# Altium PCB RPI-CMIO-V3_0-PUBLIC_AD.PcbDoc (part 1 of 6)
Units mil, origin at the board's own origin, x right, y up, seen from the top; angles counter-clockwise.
Board outline 3295.4 x 4105.44 mil, 6 copper layers (TOP, GNDT, PWRT, PWRB, GNDB, BOTTOM); 114 components, 152 nets, 703 pads, 476 vias.
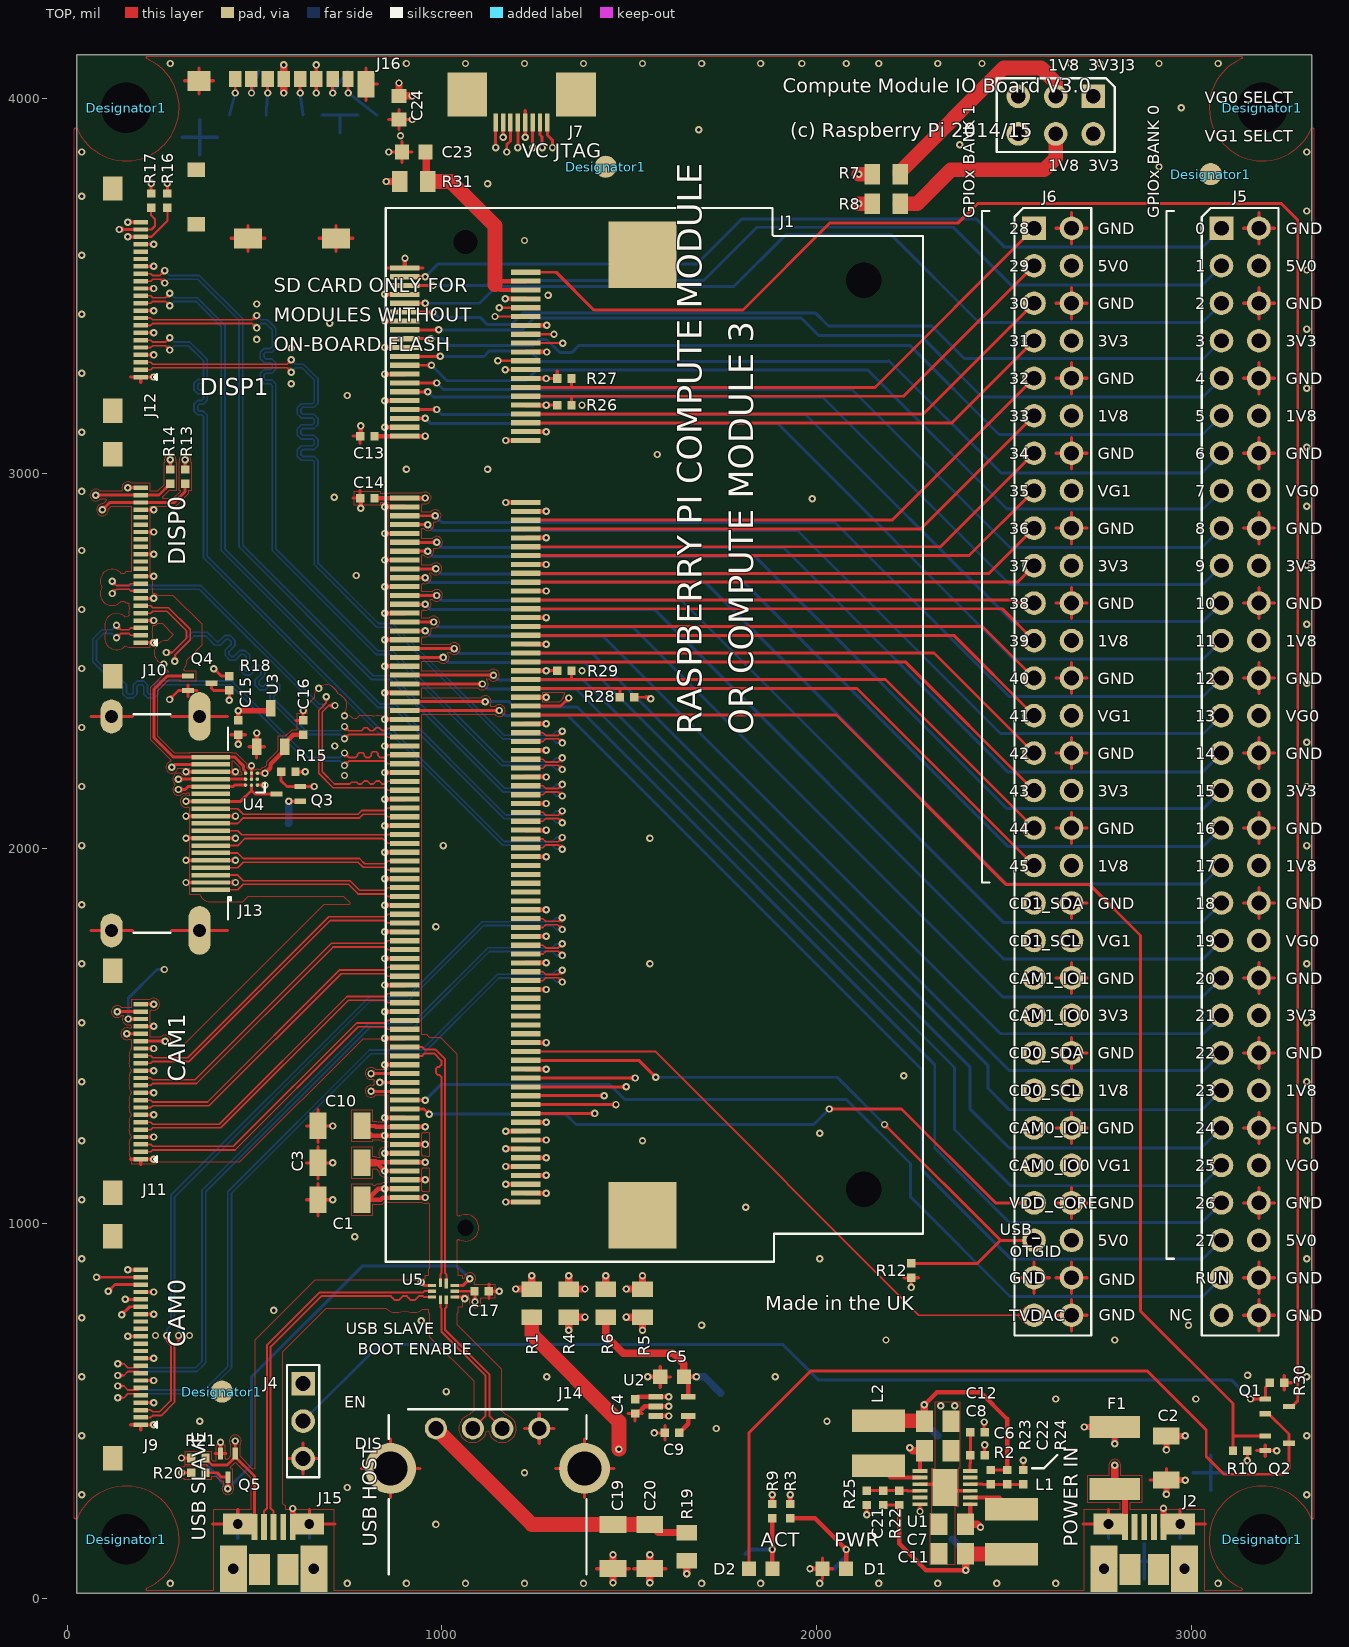
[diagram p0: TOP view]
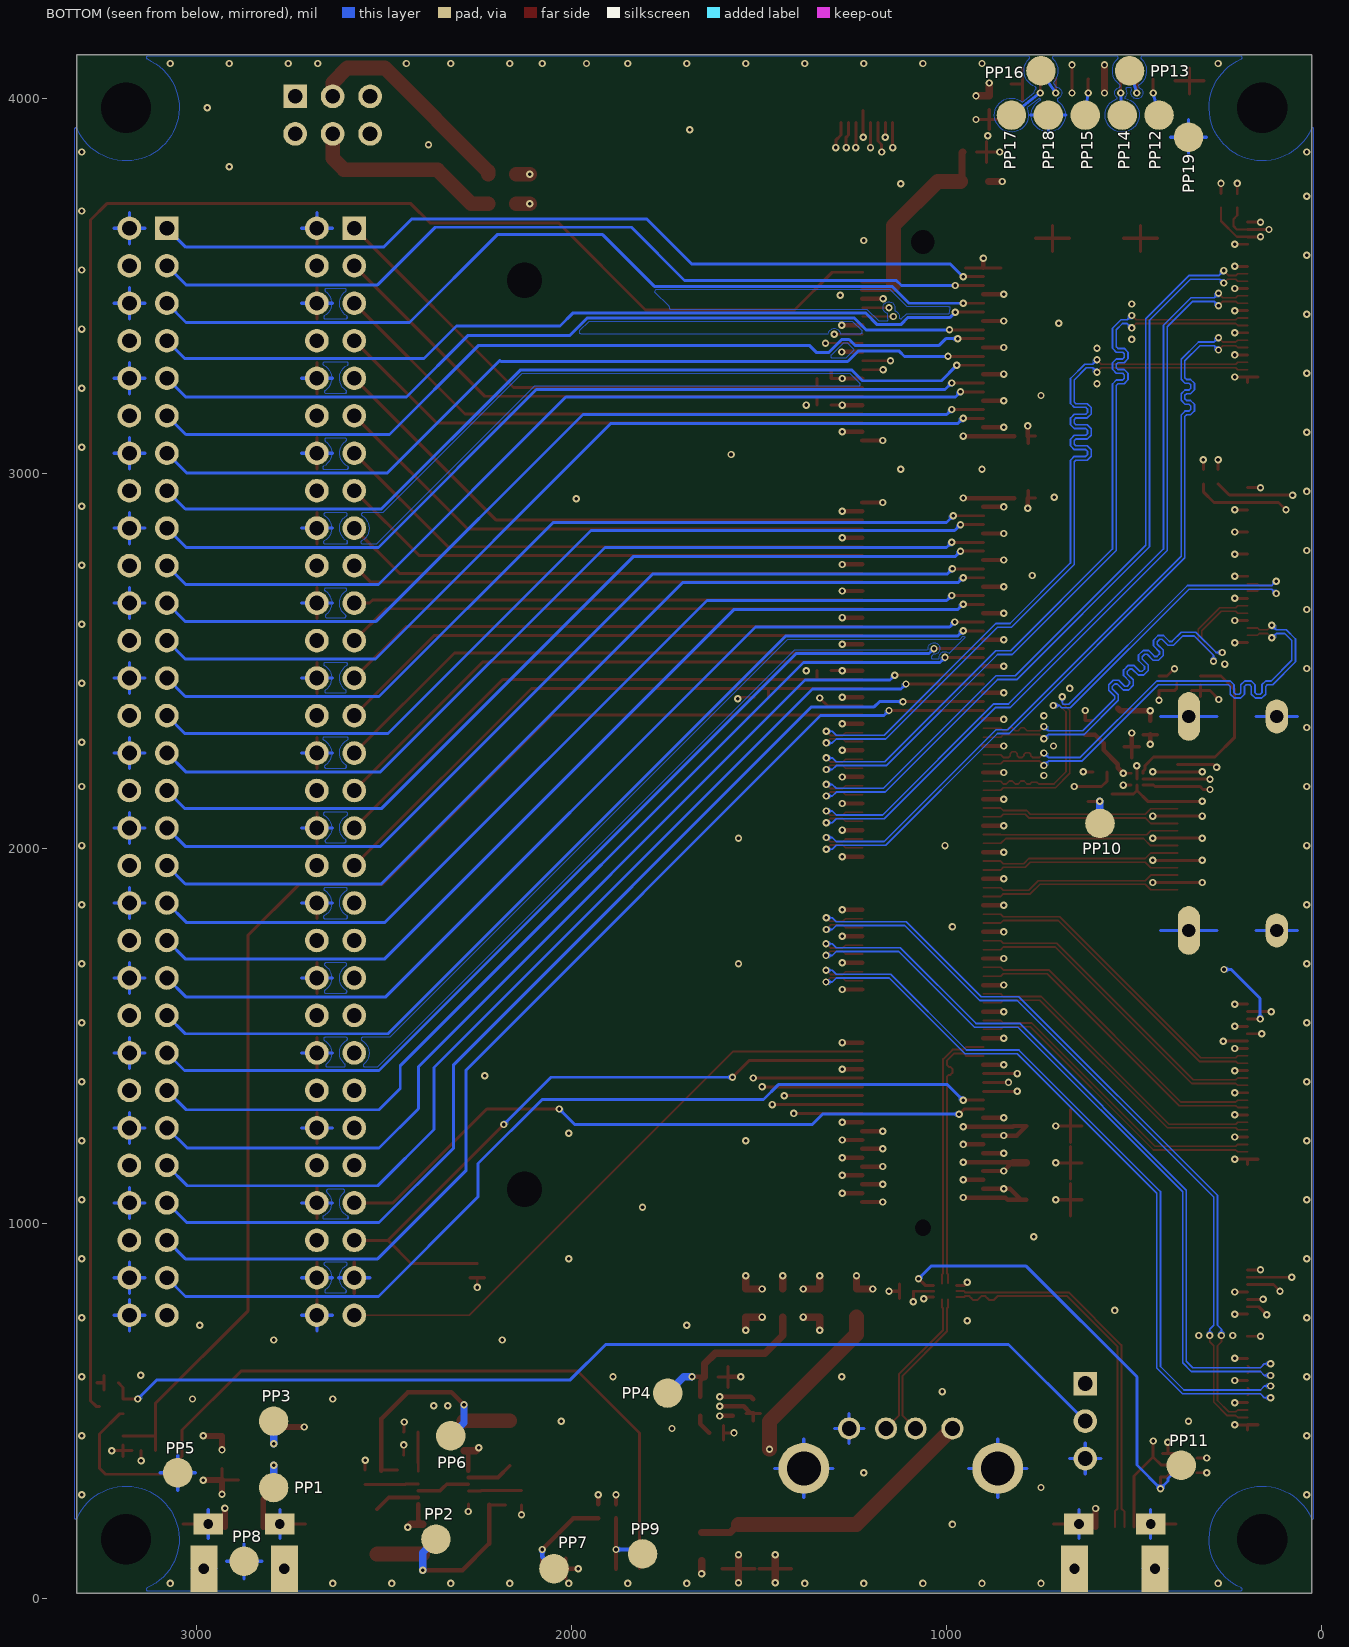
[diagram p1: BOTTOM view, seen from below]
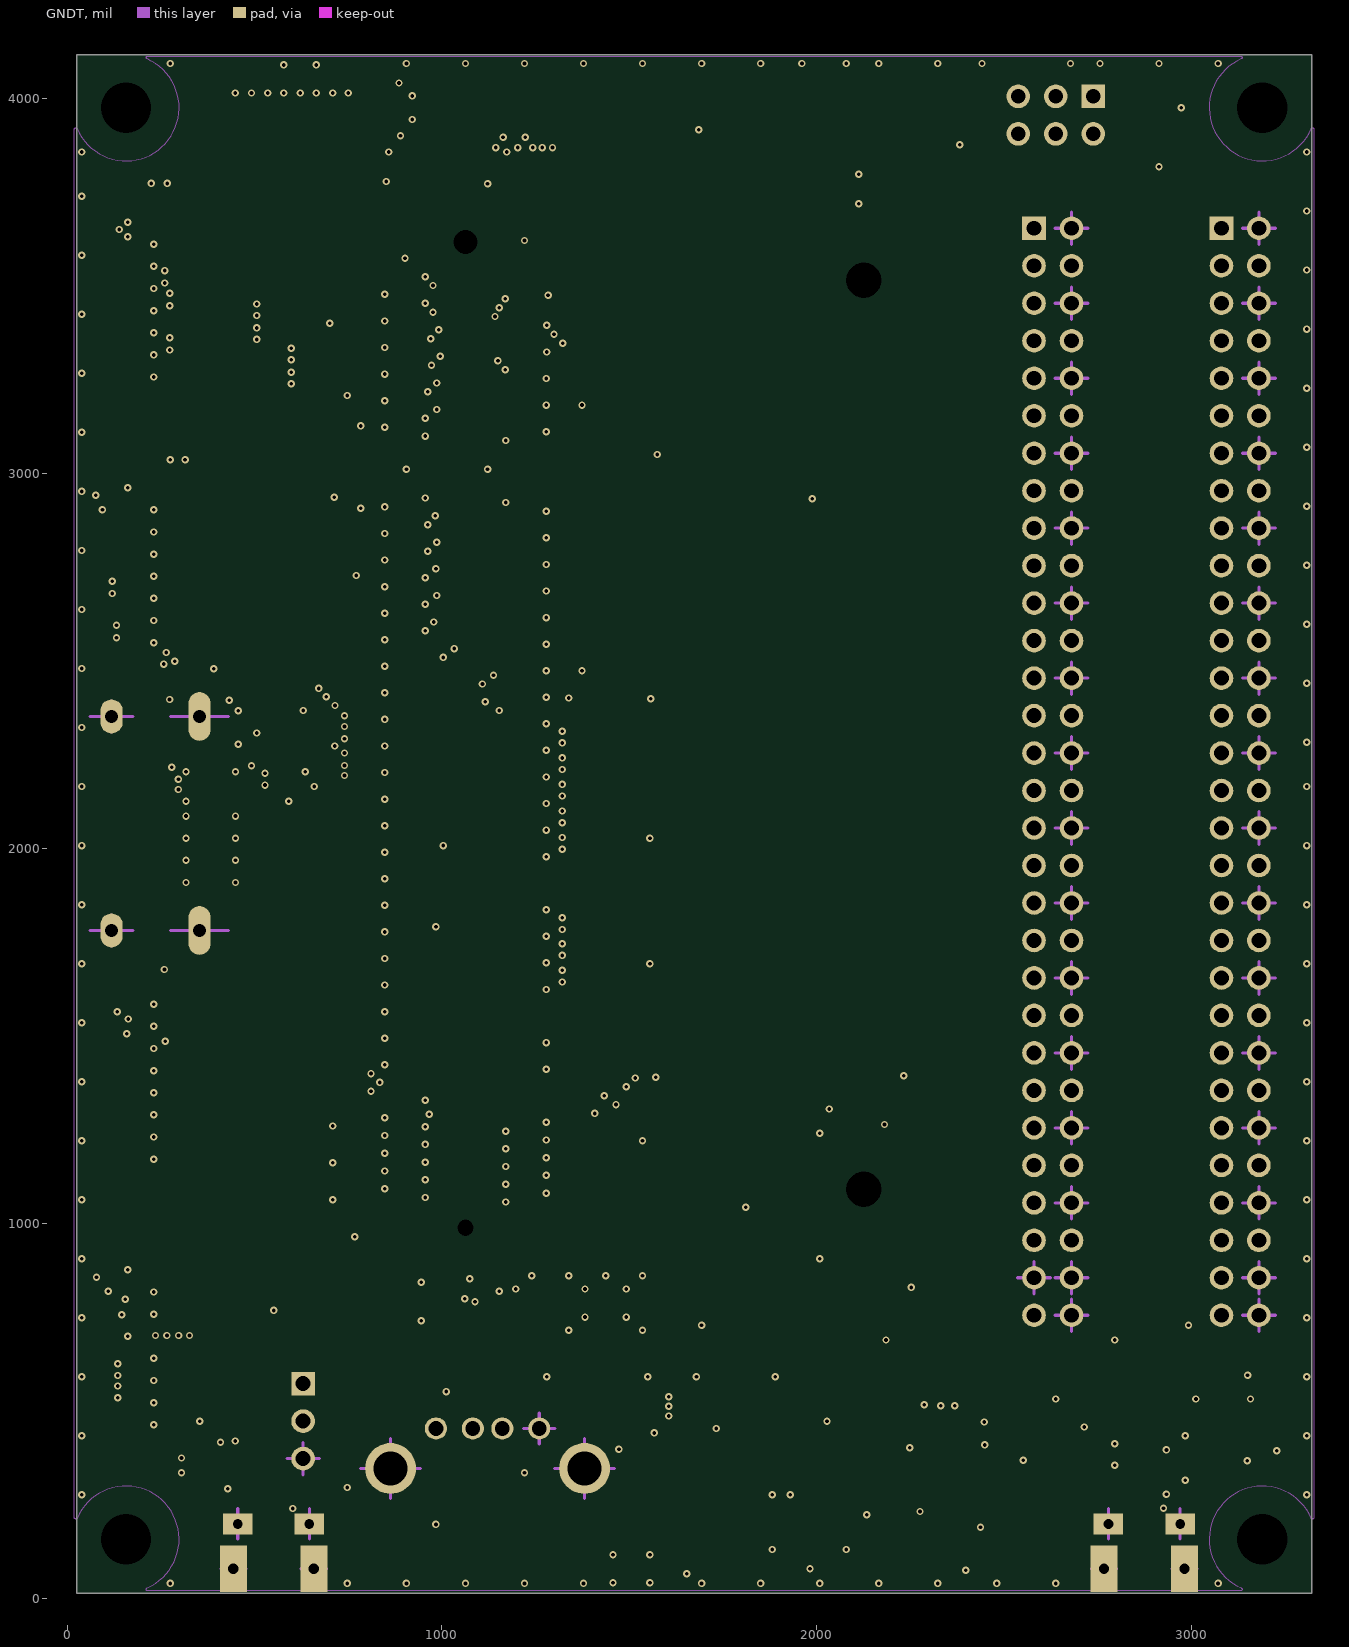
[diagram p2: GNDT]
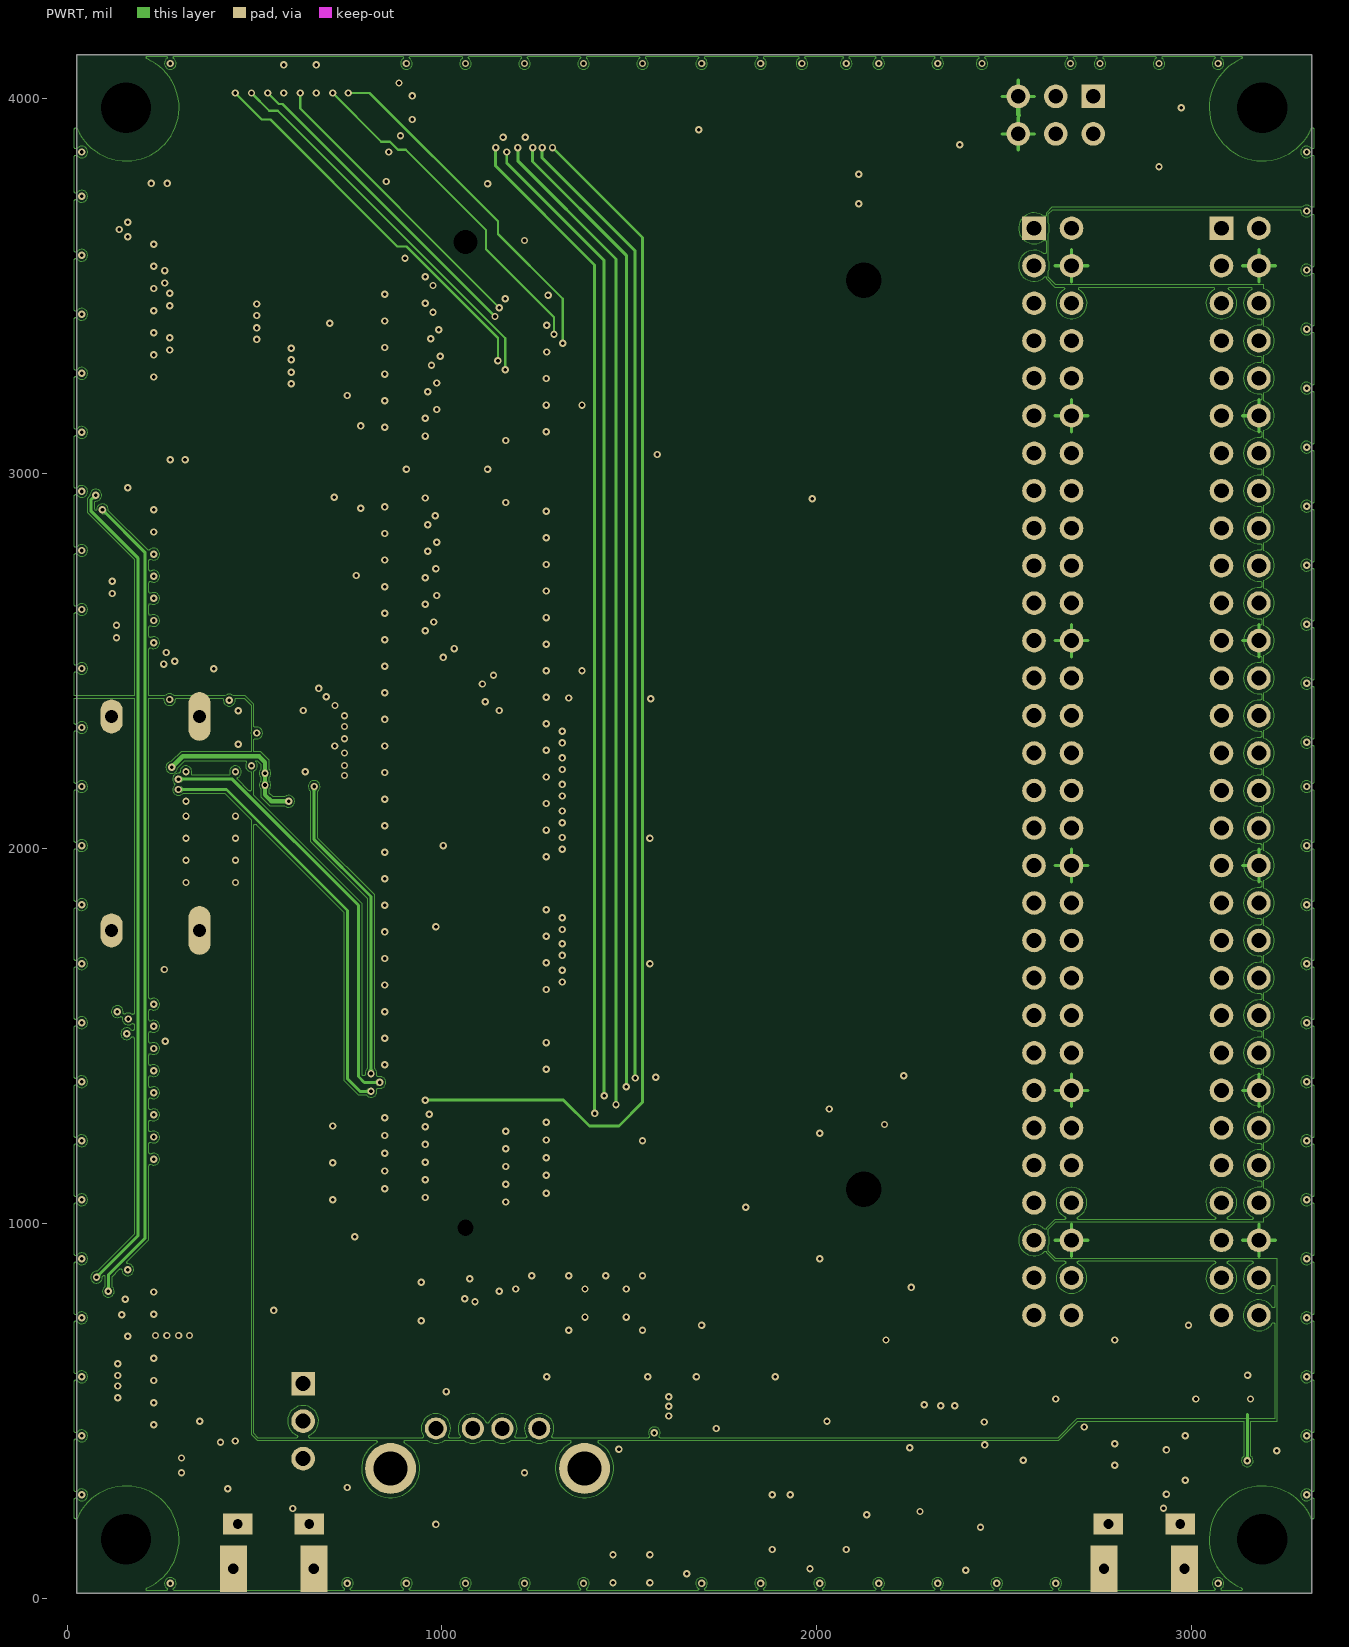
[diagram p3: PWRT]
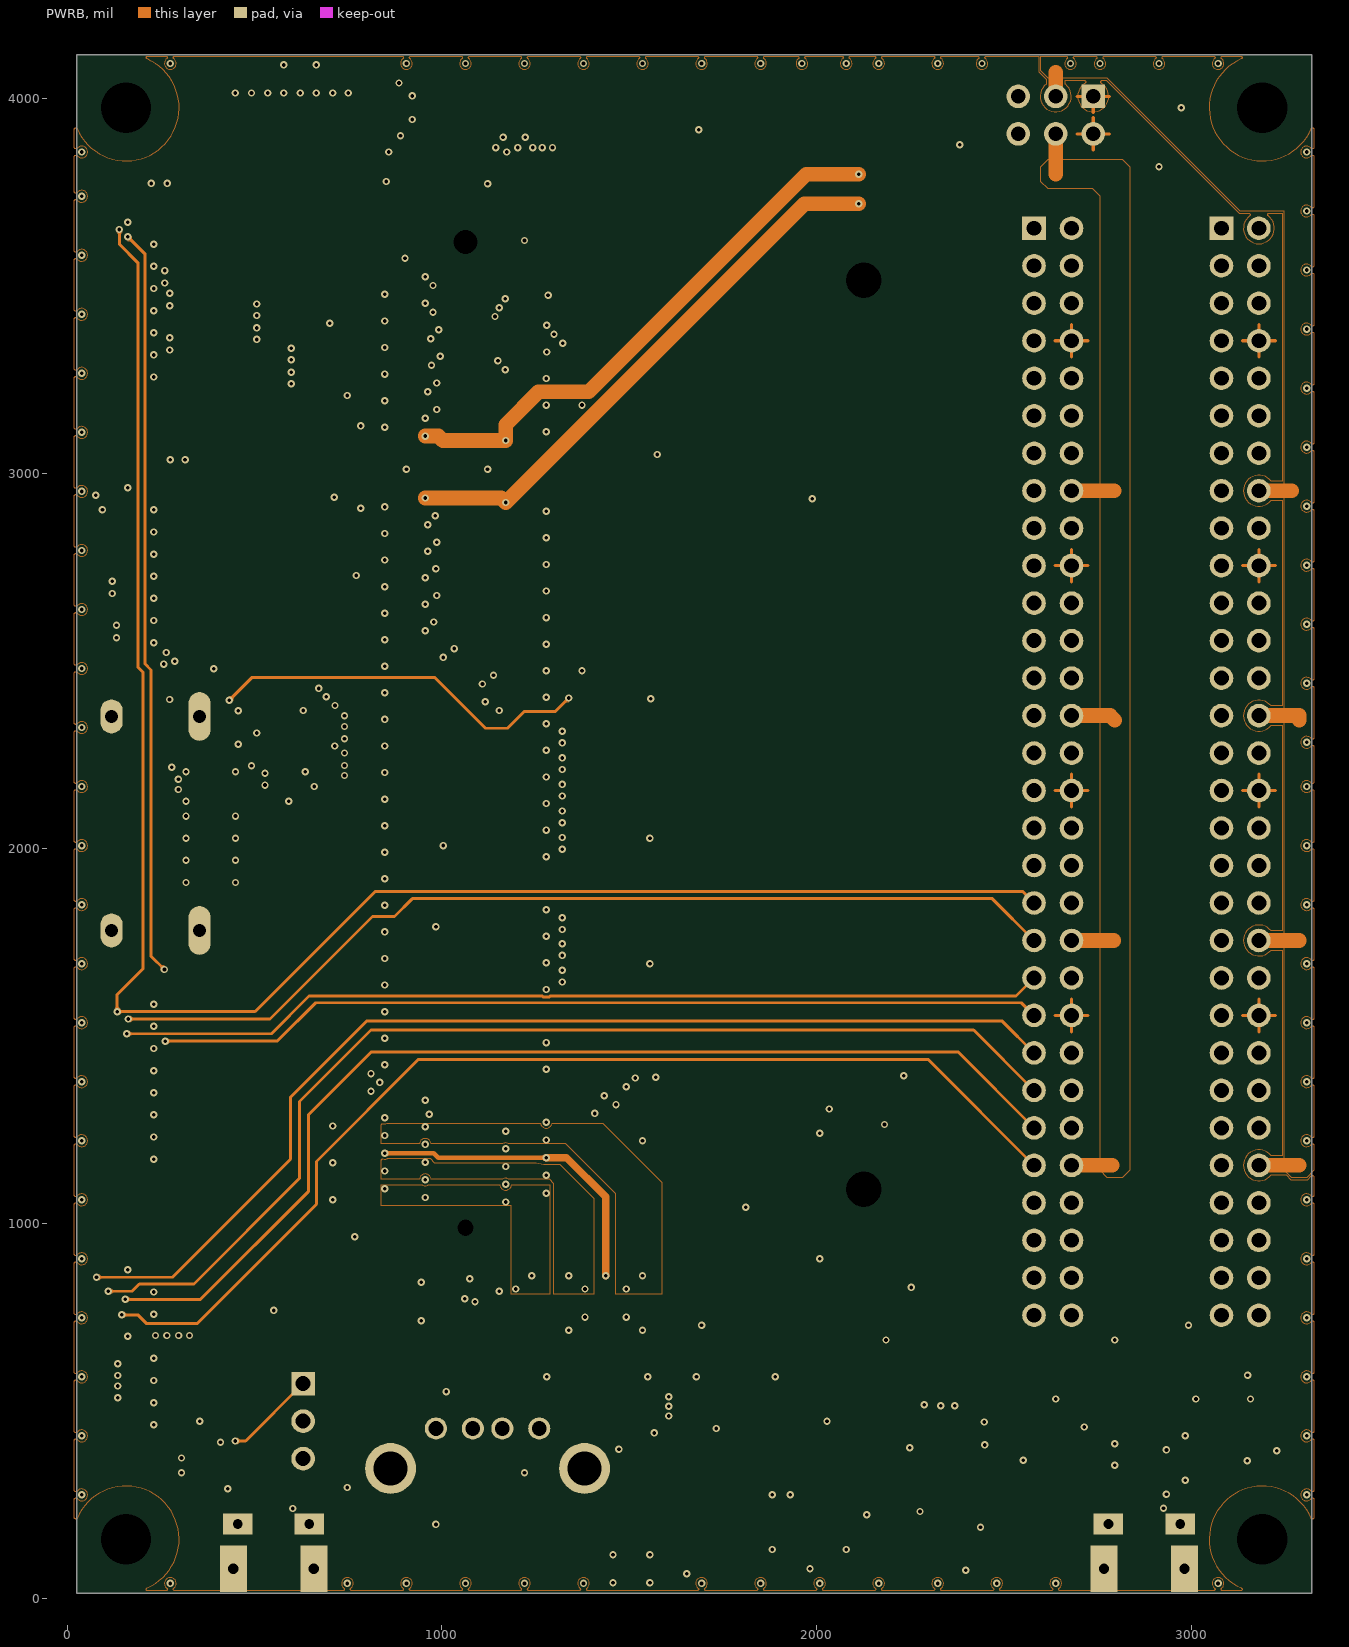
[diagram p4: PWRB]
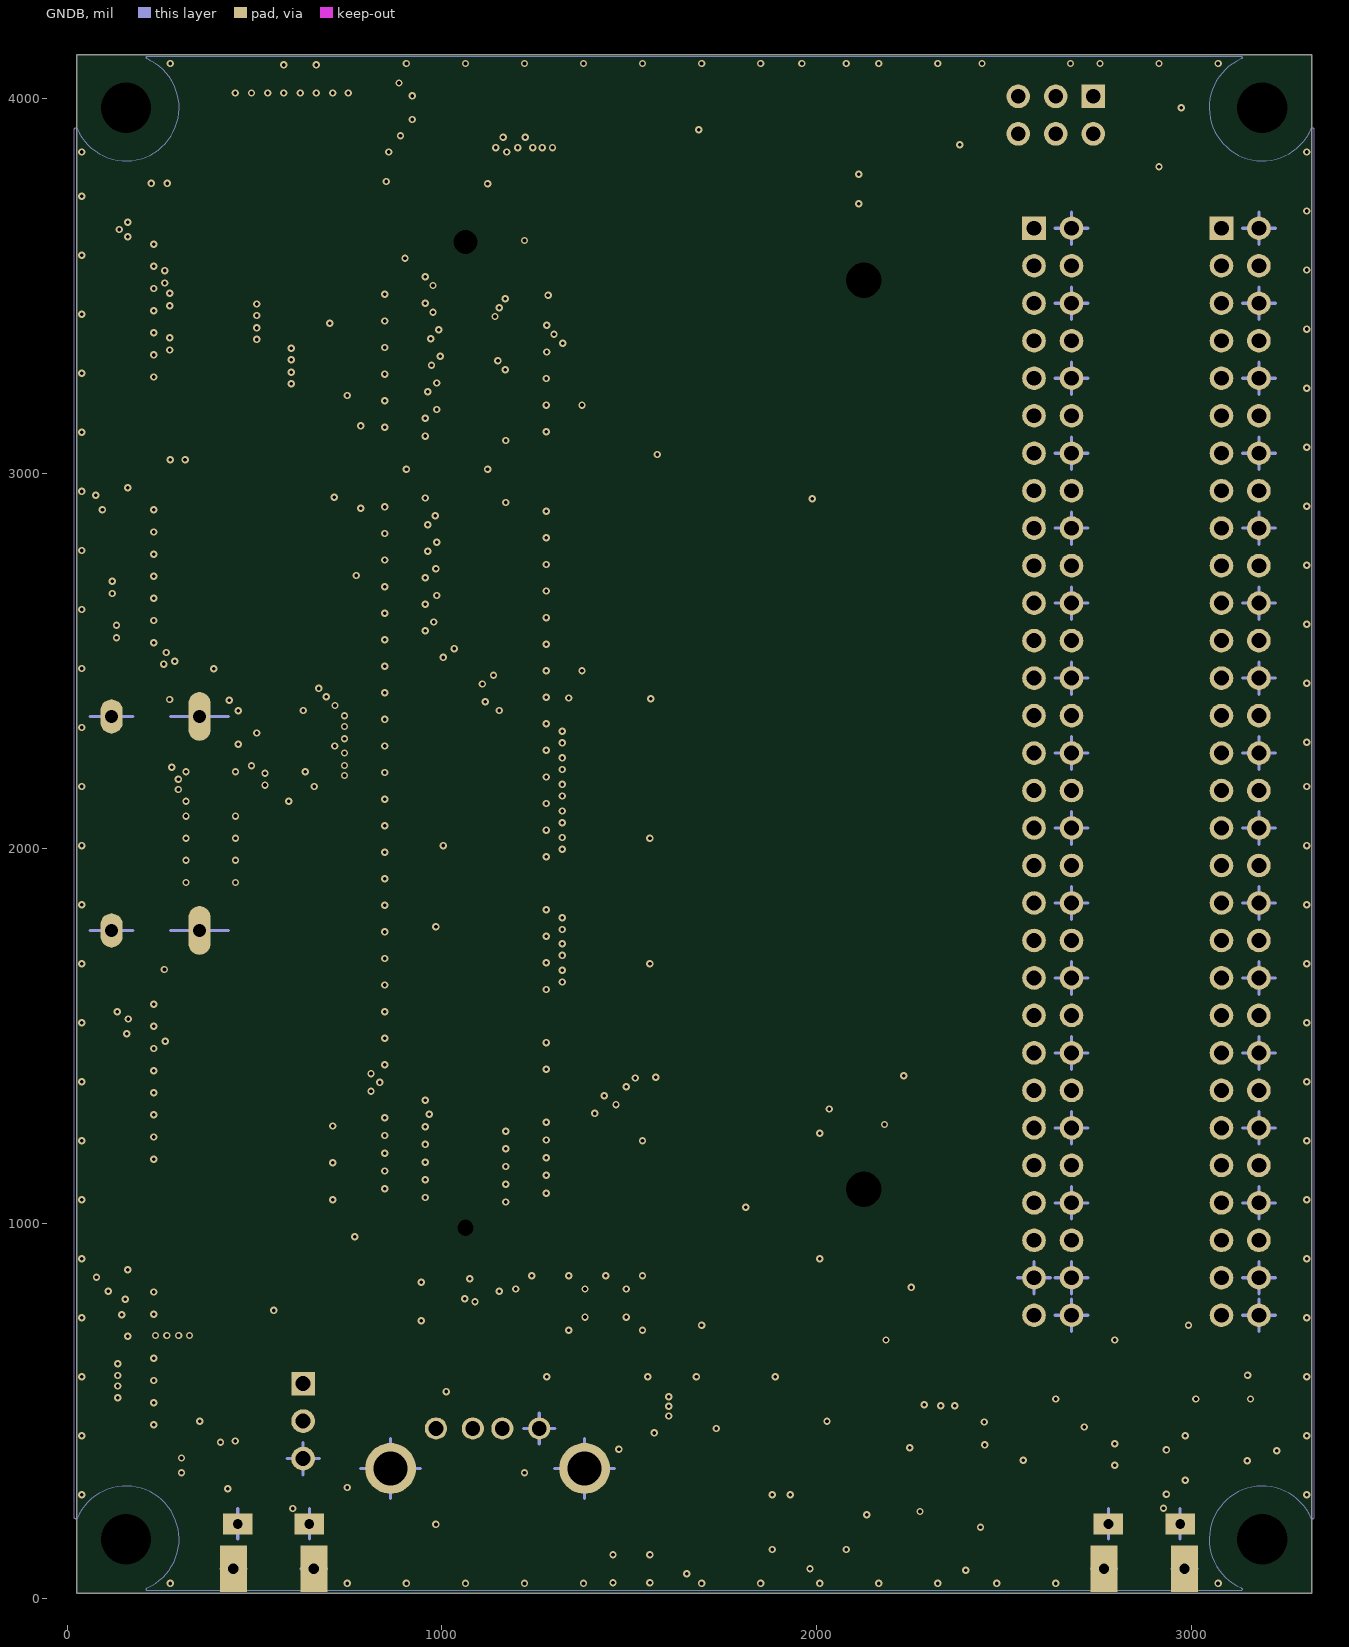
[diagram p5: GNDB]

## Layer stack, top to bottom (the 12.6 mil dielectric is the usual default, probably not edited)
TOP: signal copper 1.2
Dielectric: core 12.6, FR-4, Dk 4.8
GNDT: signal copper 1.2
Dielectric: core 12.6, FR-4, Dk 4.8
PWRT: signal copper 1.2
Dielectric: core 12.6, FR-4, Dk 4.8
PWRB: signal copper 1.2
Dielectric: core 12.6, FR-4, Dk 4.8
GNDB: signal copper 1.2
Dielectric: core 12.6, FR-4, Dk 4.8
BOTTOM: signal copper 1.4

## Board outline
25.53,12.73 3320.93,12.73 3320.93,4118.17 25.53,4118.17

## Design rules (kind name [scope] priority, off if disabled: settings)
Clearance [All] p1: gap=10
PolygonConnect [All] p1: connectstyle=Relief reliefconductorwidth=10 reliefentries=4 polygonreliefangle="90 Angle"
RoutingVias [All] p1: holewidth=28 width=50 viastyle="Through Hole" minholewidth=28 minwidth=50 maxholewidth=28 maxwidth=50
SilkscreenOverComponentPads [All] p1: minsilkscreentomaskgap=10
SolderMaskExpansion [All] p1: expansion=4
TestPointUsage [All] p1: valid=0 allowmultiple=FALSE
Testpoint [All] p1: side=15 testpointundercomponent=TRUE minsize=40 maxsize=100 preferedsize=60 minholesize=0 maxholesize=40 preferedholesize=32 testpointgrid=1 style=1023 order=0123456789
Width [All] p1: maxlimit=10 minlimit=10 preferedwidth=10
23 further rules are at their usual default settings.

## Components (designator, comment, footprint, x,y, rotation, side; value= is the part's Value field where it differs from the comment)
C1 "Comment" CAPC3216X180N 728.35,1062.99 r180 top
C2 "Comment" CAPC3216X180N 2933.07,374.02 r270 top
C3 "Comment" CAPC3216X180N 728.35,1161.42 r180 top
C4 "Comment" CAPC1005X55N 1515.75,511.81 r270 top
C5 "Comment" CAPC1608X90N 1614.17,590.55 r180 top
C6 "Comment" CAPC1005X55N 2429.13,442.91 r0 top
C7 "Comment" CAPC2012X145N 2362.2,196.85 r180 top
C8 "Comment" CAPC2012X145N 2322.84,393.7 r0 top
C9 "Comment" CAPC1005X55N 1614.17,440.94 r180 top
C10 "Comment" CAPC3216X180N 728.35,1259.84 r180 top
C11 "Comment" CAPC2012X145N 2362.2,118.11 r180 top
C12 "Comment" CAPC2012X145N 2322.84,472.44 r0 top
C13 "Comment" CAPC1005X55N 801.18,3100.39 r180 top
C14 "Comment" CAPC1005X55N 801.18,2935.04 r180 top
C15 "Comment" CAPC1005X55N 456.69,2322.84 r270 top
C16 "Comment" CAPC1005X55N 629.92,2322.84 r90 top
C17 "Comment" CAPC1005X55N 1106.3,818.9 r180 top
C19 "Comment" CAPC3216X180N 1456.69,137.8 r270 top
C20 "Comment" CAPC3216X180N 1555.12,137.8 r270 top
C21 "Comment" CAPC1005X55N 2177.16,267.72 r90 top
C22 "Comment" CAPC1005X55N 2507.87,322.84 r270 top
C23 "Comment" CAPC1608X90N 925.2,3858.27 r180 top
C24 "Comment" CAPC1608X90N 885.83,3976.38 r270 top
D1 "Comment" LEDC1608X80N 2047.24,78.74 r0 top
D2 "Comment" LEDC1608X80N 1850.39,78.74 r0 top
Designator1 "Comment" FIDUCIAL_3MM_1P5MM 1437.01,3818.9 r0 top
Designator1 "Comment" FIDUCIAL_3MM_1P5MM 3051.18,3799.21 r0 top
Designator1 "Comment" FIDUCIAL_3MM_1P5MM 413.39,551.18 r0 top
Designator1 "Comment" RPI_IMPEDANCE_TABLE 4330.71,1338.58 r0 top
Designator1 "Comment" RPI_LAYERDETAILS_6L 0,6535.43 r0 top
Designator1 "Comment" RPI_MFR_DETAILS 4330.71,2559.05 r0 top
Designator1 "Comment" RPI_LAYERDETAILS_OTHER 0,5078.74 r0 top
Designator1 "Comment" RPI_TITLEBLOCK 4330.71,0 r0 top
Designator1 "Comment" MH_NPTH_M3MECH 3188.98,157.48 r0 top
Designator1 "Comment" MH_NPTH_M3MECH 157.48,157.48 r0 top
Designator1 "Comment" MH_NPTH_M3MECH 3188.98,3976.38 r0 top
Designator1 "Comment" MH_NPTH_M3MECH 157.48,3976.38 r0 top
F1 "Comment" BOURNS_MF-MSMF150 2795.28,374.02 r90 top
J1 "Comment" FCI_10033853_CM 1062.99,2303.15 r90 top
J2 "Comment" FCI_10103594-0001LF 2874.02,78.74 r0 top
J3 "Comment" PINHDR_6W_2P54MM 2637.8,3956.69 r180 top
J4 "Comment" PINHDR_3W_2P54MM 629.92,472.44 r270 top
J5 "Comment" PINHDR_60W_2P54MM 3129.92,2204.72 r270 top
J6 "Comment" PINHDR_60W_2P54MM 2629.92,2204.72 r270 top
J7 "Comment" WE_68710814522 1212.6,3937.01 r180 top
J9 "Comment" MOLEX_54548-2271 196.85,669.29 r270 top
J10 "Comment" MOLEX_54548-2271 196.85,2755.91 r270 top
J11 "Comment" MOLEX_54548-2271 196.85,1377.95 r270 top
J12 "Comment" MOLEX_54548-2271 196.85,3464.57 r270 top
J13 "Comment" MOLEX_47151-1051 236.22,2066.93 r270 top
J14 "Comment" WURTH_61400416021 1122.05,452.76 r90 top
J15 "Comment" FCI_10103594-0001LF 551.18,78.74 r0 top
J16 "Comment" MOLEX_1040310811 570.87,3858.27 r180 top
L1 "Comment" BOURNS_SRN4018 2519.68,177.16 r270 top
L2 "Comment" BOURNS_SRN4018 2165.35,413.39 r90 top
PP1 "Comment" PP_SMT_R2MM 2795.28,295.28 r0 bottom
PP2 "Comment" PP_SMT_R2MM 2362.2,157.48 r0 bottom
PP3 "Comment" PP_SMT_R2MM 2795.28,472.44 r0 bottom
PP4 "Comment" PP_SMT_R2MM 1744.09,547.24 r0 bottom
PP5 "Comment" PP_SMT_R2MM 3051.18,334.65 r0 bottom
PP6 "Comment" PP_SMT_R2MM 2322.84,433.07 r0 bottom
PP7 "Comment" PP_SMT_R2MM 2047.24,78.74 r0 bottom
PP8 "Comment" PP_SMT_R2MM 2874.02,98.42 r0 bottom
PP9 "Comment" PP_SMT_R2MM 1811.02,118.11 r0 bottom
PP10 "Comment" PP_SMT_R2MM 590.55,2066.93 r0 bottom
PP11 "Comment" PP_SMT_R2MM 374.02,354.33 r0 bottom
PP12 "Comment" PP_SMT_R2MM 433.07,3956.69 r0 bottom
PP13 "Comment" PP_SMT_R2MM 511.81,4074.8 r0 bottom
PP14 "Comment" PP_SMT_R2MM 531.5,3956.69 r0 bottom
PP15 "Comment" PP_SMT_R2MM 629.92,3956.69 r0 bottom
PP16 "Comment" PP_SMT_R2MM 748.03,4074.8 r0 bottom
PP17 "Comment" PP_SMT_R2MM 826.77,3956.69 r0 bottom
PP18 "Comment" PP_SMT_R2MM 728.35,3956.69 r0 bottom
PP19 "Comment" PP_SMT_R2MM 354.33,3897.64 r0 bottom
Q1 "Comment" SOT50P160X90-3N 3228.35,511.81 r0 top
Q2 "Comment" SOT50P160X90-3N 3228.35,413.39 r0 top
Q3 "Comment" SOT50P160X90-3N 590.55,2145.67 r180 top
Q4 "Comment" SOT50P160X90-3N 354.33,2440.95 r0 top
Q5 "Comment" SOT50P160X90-3N 429.13,354.33 r270 top
R1 "Comment" RESC2012X65N 1240.16,787.4 r90 top
R2 "Comment" RESC1005X40N 2429.13,381.89 r180 top
R3 "Comment" RESC1005X40N 1929.13,232.28 r270 top
R4 "Comment" RESC2012X65N 1338.58,787.4 r90 top
R5 "Comment" RESC2012X65N 1535.43,787.4 r90 top
R6 "Comment" RESC2012X65N 1437.01,787.4 r90 top
R7 "Comment" RESC2012X65N 2185.04,3799.21 r0 top
R8 "Comment" RESC2012X65N 2185.04,3720.47 r0 top
R9 "Comment" RESC1005X40N 1881.89,232.28 r270 top
R10 "Comment" RESC1005X40N 3129.92,393.7 r180 top
R12 "Comment" RESC1005X40N 2251.97,874.02 r90 top
R13 "Comment" RESC1005X40N 314.96,2992.13 r270 top
R14 "Comment" RESC1005X40N 275.59,2992.13 r270 top
R15 "Comment" RESC1005X40N 590.55,2204.72 r0 top
R16 "Comment" RESC1005X40N 267.72,3728.35 r270 top
R17 "Comment" RESC1005X40N 224.41,3728.35 r270 top
R18 "Comment" RESC1005X40N 433.07,2440.95 r270 top
R19 "Comment" RESC2012X65N 1653.54,137.8 r90 top
R20 "Comment" RESC1005X40N 350.39,334.65 r0 top
R21 "Comment" RESC1005X40N 350.39,374.02 r180 top
R22 "Comment" RESC1005X40N 2220.47,267.72 r90 top
R23 "Comment" RESC1005X40N 2464.57,322.84 r270 top
R24 "Comment" RESC1005X40N 2551.18,322.84 r90 top
R25 "Comment" RESC1005X40N 2133.86,267.72 r270 top
R26 "Comment" RESC1005X40N 1326.77,3183.07 r180 top
R27 "Comment" RESC1005X40N 1326.77,3253.94 r180 top
R28 "Comment" RESC1005X40N 1494.09,2403.54 r0 top
R29 "Comment" RESC1005X40N 1326.77,2474.41 r180 top
R30 "Comment" RESC1005X40N 3228.35,574.8 r0 top
R31 "Comment" RESC2012X65N 925.2,3779.53 r180 top
U1 "Comment" DIODES_PAM2306 2342.52,295.28 r0 top
U2 "Comment" SOT65P210X100-5N 1614.17,511.81 r0 top
U3 "Comment" SOT95P280X135-3N 543.31,2322.84 r90 top
U4 "Comment" ONSEMI_ESD5384 492.13,2185.04 r180 top
U5 "Comment" FAIRCHILD_FSUSB42UMX 1003.94,818.9 r270 top

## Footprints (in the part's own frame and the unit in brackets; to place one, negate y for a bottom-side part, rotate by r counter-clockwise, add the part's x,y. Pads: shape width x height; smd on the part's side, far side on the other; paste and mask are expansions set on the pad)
BOURNS_MF-MSMF150 [mm] "BOURNS_MF-MSMF150"
  rect 1.5x3.4 smd: 1(-2.1,0) 2(2.1,0)
BOURNS_SRN4018 [mm] "BOURNS_SRN4018"
  rect 1.5x3.6 smd: 1(-1.525,0) 2(1.525,0)
CAPC1005X55N [mm] "CAPC1005X55N"
  rect 0.57x0.58 smd: 1(-0.485,0) 2(0.485,0)
CAPC1608X90N [mm] "CAPC1608X90N"
  rect 0.95x1 smd: 1(-0.8,0) 2(0.8,0)
CAPC2012X145N [mm] "CAPC2012X145N"
  rect 1.15x1.45 smd: 1(-0.9,0) 2(0.9,0)
CAPC3216X180N [mm] "CAPC3216X180N"
  rect 1.15x1.8 smd: 1(-1.5,0) 2(1.5,0)
DIODES_PAM2306 [mm] "DIODES_PAM2306"
  rect 1x0.25 smd: 1(-1.7,1.125) 2(-1.7,0.675) 3(-1.7,0.225) 4(-1.7,-0.225) 5(-1.7,-0.675) 6(-1.7,-1.125) 7(1.7,-1.125) 8(1.7,-0.675) 9(1.7,-0.225) 10(1.7,0.225) 11(1.7,0.675) 12(1.7,1.125)
  rect 1.7x2.5 smd: 13(0,0)
FAIRCHILD_FSUSB42UMX [mm] "FAIRCHILD_FSUSB42UMX"
  rect 0.66x0.21 smd: 1(-0.52,0.2)
  rect 0.56x0.21 smd: 2(-0.57,-0.2) 6(0.57,-0.2) 7(0.57,0.2)
  rect 0.21x0.56 smd: 3(-0.4,-0.77) 4(0,-0.77) 5(0.4,-0.77) 8(0.4,0.77) 9(0,0.77) 10(-0.4,0.77)
FCI_10033853_CM [mm] "FCI_10033853_CM"
  rect 0.35x2 smd: 1(31.65,4.1) 2(31.35,-4.1) 3(31.05,4.1) 4(30.75,-4.1) 5(30.45,4.1) 6(30.15,-4.1) 7(29.85,4.1) 8(29.55,-4.1) 9(29.25,4.1) 10(28.95,-4.1) 11(28.65,4.1) 12(28.35,-4.1) 13(28.05,4.1) 14(27.75,-4.1) 15(27.45,4.1) 16(27.15,-4.1) 17(26.85,4.1) 18(26.55,-4.1) 19(26.25,4.1) 20(25.95,-4.1) 21(25.65,4.1) 22(25.35,-4.1) 23(25.05,4.1) 24(24.75,-4.1) 25(24.45,4.1) 26(24.15,-4.1) 27(23.85,4.1) 28(23.55,-4.1) 29(23.25,4.1) 30(22.95,-4.1) 31(22.65,4.1) 32(22.35,-4.1) 33(22.05,4.1) 34(21.75,-4.1) 35(21.45,4.1) 36(21.15,-4.1) 37(20.85,4.1) 38(20.55,-4.1) 39(20.25,4.1) 40(19.95,-4.1) 41(16.05,4.1) 42(15.75,-4.1) 43(15.45,4.1) 44(15.15,-4.1) 45(14.85,4.1) 46(14.55,-4.1) 47(14.25,4.1) 48(13.95,-4.1) 49(13.65,4.1) 50(13.35,-4.1) 51(13.05,4.1) 52(12.75,-4.1) 53(12.45,4.1) 54(12.15,-4.1) 55(11.85,4.1) 56(11.55,-4.1) 57(11.25,4.1) 58(10.95,-4.1) 59(10.65,4.1) 60(10.35,-4.1) 61(10.05,4.1) 62(9.75,-4.1) 63(9.45,4.1) 64(9.15,-4.1) 65(8.85,4.1) 66(8.55,-4.1) 67(8.25,4.1) 68(7.95,-4.1) 69(7.65,4.1) 70(7.35,-4.1) 71(7.05,4.1) 72(6.75,-4.1) 73(6.45,4.1) 74(6.15,-4.1) 75(5.85,4.1) 76(5.55,-4.1) 77(5.25,4.1) 78(4.95,-4.1) 79(4.65,4.1) 80(4.35,-4.1) 81(4.05,4.1) 82(3.75,-4.1) 83(3.45,4.1) 84(3.15,-4.1) 85(2.85,4.1) 86(2.55,-4.1) 87(2.25,4.1) 88(1.95,-4.1) 89(1.65,4.1) 90(1.35,-4.1) 91(1.05,4.1) 92(0.75,-4.1) 93(0.45,4.1) 94(0.15,-4.1) 95(-0.15,4.1) 96(-0.45,-4.1) 97(-0.75,4.1) 98(-1.05,-4.1) 99(-1.35,4.1) 100(-1.65,-4.1) 101(-1.95,4.1) 102(-2.25,-4.1) 103(-2.55,4.1) 104(-2.85,-4.1) 105(-3.15,4.1) 106(-3.45,-4.1) 107(-3.75,4.1) 108(-4.05,-4.1) 109(-4.35,4.1) 110(-4.65,-4.1) 111(-4.95,4.1) 112(-5.25,-4.1) 113(-5.55,4.1) 114(-5.85,-4.1) 115(-6.15,4.1) 116(-6.45,-4.1) 117(-6.75,4.1) 118(-7.05,-4.1) 119(-7.35,4.1) 120(-7.65,-4.1) 121(-7.95,4.1) 122(-8.25,-4.1) 123(-8.55,4.1) 124(-8.85,-4.1) 125(-9.15,4.1) 126(-9.45,-4.1) 127(-9.75,4.1) 128(-10.05,-4.1) 129(-10.35,4.1) 130(-10.65,-4.1) 131(-10.95,4.1) 132(-11.25,-4.1) 133(-11.55,4.1) 134(-11.85,-4.1) 135(-12.15,4.1) 136(-12.45,-4.1) 137(-12.75,4.1) 138(-13.05,-4.1) 139(-13.35,4.1) 140(-13.65,-4.1) 141(-13.95,4.1) 142(-14.25,-4.1) 143(-14.55,4.1) 144(-14.85,-4.1) 145(-15.15,4.1) 146(-15.45,-4.1) 147(-15.75,4.1) 148(-16.05,-4.1) 149(-16.35,4.1) 150(-16.65,-4.1) 151(-16.95,4.1) 152(-17.25,-4.1) 153(-17.55,4.1) 154(-17.85,-4.1) 155(-18.15,4.1) 156(-18.45,-4.1) 157(-18.75,4.1) 158(-19.05,-4.1) 159(-19.35,4.1) 160(-19.65,-4.1) 161(-19.95,4.1) 162(-20.25,-4.1) 163(-20.55,4.1) 164(-20.85,-4.1) 165(-21.15,4.1) 166(-21.45,-4.1) 167(-21.75,4.1) 168(-22.05,-4.1) 169(-22.35,4.1) 170(-22.65,-4.1) 171(-22.95,4.1) 172(-23.25,-4.1) 173(-23.55,4.1) 174(-23.85,-4.1) 175(-24.15,4.1) 176(-24.45,-4.1) 177(-24.75,4.1) 178(-25.05,-4.1) 179(-25.35,4.1) 180(-25.65,-4.1) 181(-25.95,4.1) 182(-26.25,-4.1) 183(-26.55,4.1) 184(-26.85,-4.1) 185(-27.15,4.1) 186(-27.45,-4.1) 187(-27.75,4.1) 188(-28.05,-4.1) 189(-28.35,4.1) 190(-28.65,-4.1) 191(-28.95,4.1) 192(-29.25,-4.1) 193(-29.55,4.1) 194(-29.85,-4.1) 195(-30.15,4.1) 196(-30.45,-4.1) 197(-30.75,4.1) 198(-31.05,-4.1) 199(-31.35,4.1) 200(-31.65,-4.1)
  round 0.5 hole 1.1 unplated: ""(-33.4,0)
  rect 4.5x4.6 smd: ""(-32.55,-12) ""(32.55,-12)
  round 1 hole 2.4 unplated: ""(-30.8,-27) ""(30.8,-27)
  round 1 hole 1.6 unplated: ""(33.4,0)
  silkscreen extent -35.7,-31 35.7,5.4
FCI_10103594-0001LF [mm] "FCI_10103594-0001LF"
  rect 0.4x1.75 smd: 1(-1.3,2.825) 2(-0.65,2.825) 3(0,2.825) 4(0.65,2.825) 5(1.3,2.825)
  rect 2x1.45 hole 0.65: 6(-2.425,3.03) 8(2.425,3.03)
  rect 1.825x3.15 hole 0.7: 7(-2.725,0) 9(2.725,0)
  rect 1.42x2.1 smd: ""(-0.96,-0.05) ""(0.96,-0.05)
FIDUCIAL_3MM_1P5MM [mm] "FIDUCIAL_3MM_1P5MM"
  round 1.5 smd: ""(0,0)
LEDC1608X80N [mm] "LEDC1608X80N"
  rect 0.95x1 smd: 1(-0.8,0) 2(0.8,0)
MH_NPTH_M3MECH [mm] "MH_NPTH_M3MECH"
  round 0.5 hole 3.4 unplated: ""(0,0)
MOLEX_47151-1051 [mm] "MOLEX_47151-1051"
  rect 0.3x2.6 smd: 1(4.5,3.74) 2(4,3.74) 3(3.5,3.74) 4(3,3.74) 5(2.5,3.74) 6(2,3.74) 7(1.5,3.74) 8(1,3.74) 9(0.5,3.74) 10(0,3.74) 11(-0.5,3.74) 12(-1,3.74) 13(-1.5,3.74) 14(-2,3.74) 15(-2.5,3.74) 16(-3,3.74) 17(-3.5,3.74) 18(-4,3.74) 19(-4.5,3.74)
  oval 3.3x1.5 hole 0.9: 20(7.25,2.98) 22(-7.25,2.98)
  oval 2.3x1.5 hole 0.9: 21(7.25,-2.98) 23(-7.25,-2.98)
  silkscreen extent -7.4,-1.5 7.4,5.1
MOLEX_54548-2271 [mm] "MOLEX_54548-2271"
  rect 0.3x1 smd: 1(5.25,0) 2(4.75,0) 3(4.25,0) 4(3.75,0) 5(3.25,0) 6(2.75,0) 7(2.25,0) 8(1.75,0) 9(1.25,0) 10(0.75,0) 11(0.25,0) 12(-0.25,0) 13(-0.75,0) 14(-1.25,0) 15(-1.75,0) 16(-2.25,0) 17(-2.75,0) 18(-3.25,0) 19(-3.75,0) 20(-4.25,0) 21(-4.75,0) 22(-5.25,0)
  rect 1.65x1.3 smd: ""(-7.525,-1.9) ""(7.525,-1.9)
  silkscreen extent 5.05,0.9 5.45,1.1
MOLEX_1040310811 [mm] "MOLEX_1040310811"
  rect 0.85x1.1 smd: 1(3.105,-4.95) 2(2.005,-4.95) 3(0.905,-4.95) 4(-0.195,-4.95) 5(-1.295,-4.95) 6(-2.395,-4.95) 7(-3.495,-4.95)
  rect 0.75x1.1 smd: 8(-4.545,-4.95)
  rect 1.2x1 smd: 9(5.74,1.2) 10(5.74,4.9)
  rect 1.17x1.8 smd: 11(-5.755,-4.6)
  rect 1.55x1.35 smd: 12(5.565,-4.825)
  rect 1.9x1.35 smd: 13(2.24,5.85) 14(-3.73,5.85)
ONSEMI_ESD5384 [mm] "ONSEMI_ESD5384"
  round 0.235 smd: A1(-0.4,0.4) A2(0,0.4) A3(0.4,0.4) B1(-0.4,0) B2(0,0) B3(0.4,0) C1(-0.4,-0.4) C2(0,-0.4) C3(0.4,-0.4)
  silkscreen extent -0.9,0.3 -0.3,0.9
PINHDR_3W_2P54MM [mm] "PINHDR_3W_2P54MM"
  rect 1.6x1.6 hole 1: 1(-2.54,0)
  round 1.6 hole 1: 2(0,0) 3(2.54,0)
  silkscreen extent -3.8,-1.1 3.8,1.1
PINHDR_6W_2P54MM [mm] "PINHDR_6W_2P54MM"
  rect 1.6x1.6 hole 1: 1(-2.54,-1.27)
  round 1.6 hole 1: 2(-2.54,1.27) 3(0,-1.27) 4(0,1.27) 5(2.54,-1.27) 6(2.54,1.27)
  silkscreen extent -4,-2.5 4,2.5
PINHDR_60W_2P54MM [mm] "PINHDR_60W_2P54MM"
  rect 1.6x1.6 hole 1: 1(-36.83,-1.27)
  round 1.6 hole 1: 2(-36.83,1.27) 3(-34.29,-1.27) 4(-34.29,1.27) 5(-31.75,-1.27) 6(-31.75,1.27) 7(-29.21,-1.27) 8(-29.21,1.27) 9(-26.67,-1.27) 10(-26.67,1.27) 11(-24.13,-1.27) 12(-24.13,1.27) 13(-21.59,-1.27) 14(-21.59,1.27) 15(-19.05,-1.27) 16(-19.05,1.27) 17(-16.51,-1.27) 18(-16.51,1.27) 19(-13.97,-1.27) 20(-13.97,1.27) 21(-11.43,-1.27) 22(-11.43,1.27) 23(-8.89,-1.27) 24(-8.89,1.27) 25(-6.35,-1.27) 26(-6.35,1.27) 27(-3.81,-1.27) 28(-3.81,1.27) 29(-1.27,-1.27) 30(-1.27,1.27) 31(1.27,-1.27) 32(1.27,1.27) 33(3.81,-1.27) 34(3.81,1.27) 35(6.35,-1.27) 36(6.35,1.27) 37(8.89,-1.27) 38(8.89,1.27) 39(11.43,-1.27) 40(11.43,1.27) 41(13.97,-1.27) 42(13.97,1.27) 43(16.51,-1.27) 44(16.51,1.27) 45(19.05,-1.27) 46(19.05,1.27) 47(21.59,-1.27) 48(21.59,1.27) 49(24.13,-1.27) 50(24.13,1.27) 51(26.67,-1.27) 52(26.67,1.27) 53(29.21,-1.27) 54(29.21,1.27) 55(31.75,-1.27) 56(31.75,1.27) 57(34.29,-1.27) 58(34.29,1.27) 59(36.83,-1.27) 60(36.83,1.27)
  silkscreen extent -38.2,-2.6 38.2,2.6
PP_SMT_R2MM [mm] "PP_SMT_R2MM"
  round 2 smd: 1(0,0)
RESC1005X40N [mm] "RESC1005X40N"
  rect 0.57x0.58 smd: 1(-0.485,0) 2(0.485,0)
RESC2012X65N [mm] "RESC2012X65N"
  rect 1.05x1.4 smd: 1(-0.95,0) 2(0.95,0)
RPI_IMPEDANCE_TABLE [mil] "RPI_IMPEDANCE_TABLE"
RPI_LAYERDETAILS_6L [mil] "RPI_LAYERDETAILS_6L"
RPI_LAYERDETAILS_OTHER [mil] "RPI_LAYERDETAILS_OTHER"
RPI_MFR_DETAILS [mil] "RPI_MFR_DETAILS"
RPI_TITLEBLOCK [mil] "RPI_TITLEBLOCK"
SOT50P160X90-3N [mm] "SOT50P160X90-3N"
  rect 0.8x0.35 smd: 1(-0.8,0.5) 2(-0.8,-0.5) 3(0.8,0)
SOT65P210X100-5N [mm] "SOT65P210X100-5N"
  rect 1x0.4 smd: 1(-1.1,0.65) 2(-1.1,0) 3(-1.1,-0.65) 4(1.1,-0.65) 5(1.1,0.65)
SOT95P280X135-3N [mm] "SOT95P280X135-3N"
  rect 1.1x0.65 smd: 1(-1.3,0.95) 2(-1.3,-0.95) 3(1.3,0)
WE_68710814522 [mm] "WE_68710814522"
  rect 0.3x1.2 smd: 1(-1.75,0) 2(-1.25,0) 3(-0.75,0) 4(-0.25,0) 5(0.25,0) 6(0.75,0) 7(1.25,0) 8(1.75,0)
  rect 2.7x3 smd: ""(-3.68,-1.9) ""(3.68,-1.9)
WURTH_61400416021 [mm] "WURTH_61400416021"
  round 1.5 hole 1: 1(0,3.5) 2(0,1) 3(0,-1) 4(0,-3.5)
  round 3.45 hole 2.3: 5(-2.71,6.57) 6(-2.71,-6.57)
  silkscreen extent -9.9,-6.7 1.3,6.7

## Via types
v1: diameter 19.68, hole 9.84, TOP to BOTTOM, 476 vias

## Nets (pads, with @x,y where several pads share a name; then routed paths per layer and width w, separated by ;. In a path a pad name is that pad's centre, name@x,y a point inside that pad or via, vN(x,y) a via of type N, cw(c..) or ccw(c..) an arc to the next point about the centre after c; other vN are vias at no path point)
1V8: C12.1 C22.1 J3.5 J3.6 J5.12 J5.24 J5.36 J5.48 J6.12 J6.24 J6.36 J6.48 L2.2 PP6.1 R5.1 R10.1 R18.1 R23.1 | length 2556.9
  TOP w7.87: v1(391.73,2480.04) 411.73,2460.04 R18.1@433.07,2460.04 ; R23.1@2464.57,341.93 C22.1@2507.87,341.93 ; C22.1@2506.69,341.73 C22.1@2507.87,340.55 ; v1(3148.82,366.65) 3148.82,393.5 R10.1@3149.02,393.7
  TOP w11.81: v1(2287.4,515.83) 2320.79,549.21 2437.01,549.21 2507.87,478.35 C22.1@2507.87,341.93 C22.1@2507.87,340.55
  TOP w19.68: v1(1492.13,750) R5.1@1535.43,750 v1(1535.43,714.49) ; C12.1@2287.4,472.44 v1(2287.4,515.83)
  TOP w39.37: L2.2@2165.35,473.42 2286.42,473.42 C12.1@2287.4,472.44
  PWRT w7.87: v1(3148.82,366.65) 3148.82,489.37 3149.61,490.16
  PWRT w8.46: 2494.45,3906.69 J3.6@2537.8,3906.69 ; 2494.45,4006.69 J3.5@2537.8,4006.69 ; 2537.8,3863.35 J3.6@2537.8,3906.69 ; 2537.8,3950.04 J3.6@2537.8,3906.69 ; 2537.8,4050.04 J3.5@2537.8,4006.69 ; 2581.14,3906.69 J3.6@2537.8,3906.69 ; 2581.14,4006.69 J3.5@2537.8,4006.69 ; 2636.58,1354.72 J6.48@2679.92,1354.72 ; 2636.58,1954.72 J6.36@2679.92,1954.72 ; 2636.58,2554.72 J6.24@2679.92,2554.72 ; 2636.58,3154.72 J6.12@2679.92,3154.72 ; 2679.92,1311.38 J6.48@2679.92,1354.72 ; 2679.92,1398.07 J6.48@2679.92,1354.72 ; 2679.92,1911.38 J6.36@2679.92,1954.72 ; 2679.92,1998.07 J6.36@2679.92,1954.72 ; 2679.92,2511.38 J6.24@2679.92,2554.72 ; 2679.92,2598.07 J6.24@2679.92,2554.72 ; 2679.92,3111.38 J6.12@2679.92,3154.72 ; 2679.92,3198.07 J6.12@2679.92,3154.72 ; 2723.27,1354.72 J6.48@2679.92,1354.72 ; 2723.27,1954.72 J6.36@2679.92,1954.72 ; 2723.27,2554.72 J6.24@2679.92,2554.72 ; 2723.27,3154.72 J6.12@2679.92,3154.72 ; 3136.58,1354.72 J5.48@3179.92,1354.72 ; 3136.58,1954.72 J5.36@3179.92,1954.72 ; 3136.58,2554.72 J5.24@3179.92,2554.72 ; 3136.58,3154.72 J5.12@3179.92,3154.72 ; 3179.92,1311.38 J5.48@3179.92,1354.72 ; 3179.92,1398.07 J5.48@3179.92,1354.72 ; 3179.92,1911.38 J5.36@3179.92,1954.72 ; 3179.92,1998.07 J5.36@3179.92,1954.72 ; 3179.92,2511.38 J5.24@3179.92,2554.72 ; 3179.92,2598.07 J5.24@3179.92,2554.72 ; 3179.92,3111.38 J5.12@3179.92,3154.72 ; 3179.92,3198.07 J5.12@3179.92,3154.72
  PWRT w11.81: J3.5@2537.8,4006.69 2537.8,3958.27 2539.37,3956.69
  BOTTOM w19.68: v1(2287.4,515.83) 2287.4,468.5 PP6.1@2322.84,433.07
3V3: C4.1 C11.1 C17.2 C21.1 C24.1 J3.1 J3.2 J5.8 J5.20 J5.32 J5.44 J6.8 J6.20 J6.32 J6.44 J9.22 J10.22 J11.22 J12.22 J16.4 L1.2 PP2.1 R3.1 R4.1 R9.1 R13.1 R14.1 R15.2 R16.1 R17.1 R20.1 R22.1 R31.2 U2.1 U2.3 U5.9 | length 3123
  TOP w7.87: v1(162.32,875.98) J9.22@196.85,875.98 ; v1(162.32,2962.6) J10.22@196.85,2962.6 ; v1(162.32,3671.26) J12.22@196.85,3671.26 ; J11.22@196.85,1584.65 v1(231.38,1584.65) ; R17.1@224.41,3747.44 v1(224.41,3774.41) ; R16.1@267.72,3747.44 v1(267.72,3774.41) ; R14.1@275.59,3011.02 R14.1@275.59,3011.22 v1(275.59,3037.09) ; v1(305.43,334.65) R20.1@331.3,334.65 R20.1@331.5,334.65 ; R13.1@314.96,3011.02 R13.1@314.96,3011.22 v1(314.96,3037.4) ; R15.2@609.45,2204.72 R15.2@609.65,2204.72 v1(635.51,2204.72) ; U5.9@1034.25,818.9 C17.2@1087.2,818.9 1088.58,818.9 v1(1088.58,790.94) ; C21.1@2177.16,248.62 R22.1@2220.47,248.62 ; R22.1@2219.29,250 R22.1@2220.47,248.82
  TOP w11.81: C4.1@1515.75,530.9 1522.24,537.4 U2.1@1570.87,537.4 v1(1605.39,537.4) ; U2.3@1570.87,486.22 v1(1605.39,486.22) ; R9.1@1881.89,251.18 R9.1@1881.89,251.38 v1(1881.89,275.59) ; R3.1@1929.13,251.18 R3.1@1929.13,251.38 v1(1929.13,275.59) ; R22.1@2220.47,248.82 R22.1@2220.47,248.62 2220.47,145.67 2291.42,74.72 v1(2397.64,74.72)
  TOP w19.68: v1(578.54,4015.75) J16.4@578.54,4053.15 v1(578.54,4090.55) ; v1(851.38,3779.53) R31.2@887.8,3779.53 ; v1(885.83,4042.32) C24.1@885.83,4007.87 v1(921.26,4007.87) ; v1(1338.58,714.49) R4.1@1338.58,750 v1(1381.89,750) ; v1(2397.64,74.72) C11.1@2397.64,118.11
  TOP w39.37: C11.1@2397.64,118.11 2518.7,118.11 L1.2@2519.68,117.13
  PWRB w8.46: 2636.58,1554.72 J6.44@2679.92,1554.72 ; 2636.58,2154.72 J6.32@2679.92,2154.72 ; 2636.58,2754.72 J6.20@2679.92,2754.72 ; 2636.58,3354.72 J6.8@2679.92,3354.72 ; 2679.92,1511.38 J6.44@2679.92,1554.72 ; 2679.92,1598.07 J6.44@2679.92,1554.72 ; 2679.92,2111.38 J6.32@2679.92,2154.72 ; 2679.92,2198.07 J6.32@2679.92,2154.72 ; 2679.92,2711.38 J6.20@2679.92,2754.72 ; 2679.92,2798.07 J6.20@2679.92,2754.72 ; 2679.92,3311.38 J6.8@2679.92,3354.72 ; 2679.92,3398.07 J6.8@2679.92,3354.72 ; 2694.45,3906.69 J3.2@2737.8,3906.69 ; 2694.45,4006.69 J3.1@2737.8,4006.69 ; 2723.27,1554.72 J6.44@2679.92,1554.72 ; 2723.27,2154.72 J6.32@2679.92,2154.72 ; 2723.27,2754.72 J6.20@2679.92,2754.72 ; 2723.27,3354.72 J6.8@2679.92,3354.72 ; 2737.8,3863.35 J3.2@2737.8,3906.69 ; 2737.8,3950.04 J3.2@2737.8,3906.69 ; 2737.8,3963.35 J3.1@2737.8,4006.69 ; 2781.14,3906.69 J3.2@2737.8,3906.69 ; 2781.14,4006.69 J3.1@2737.8,4006.69 ; 3136.58,1554.72 J5.44@3179.92,1554.72 ; 3136.58,2154.72 J5.32@3179.92,2154.72 ; 3136.58,2754.72 J5.20@3179.92,2754.72 ; 3136.58,3354.72 J5.8@3179.92,3354.72 ; 3179.92,1511.38 J5.44@3179.92,1554.72 ; 3179.92,1598.07 J5.44@3179.92,1554.72 ; 3179.92,2111.38 J5.32@3179.92,2154.72 ; 3179.92,2198.07 J5.32@3179.92,2154.72 ; 3179.92,2711.38 J5.20@3179.92,2754.72 ; 3179.92,2798.07 J5.20@3179.92,2754.72 ; 3179.92,3311.38 J5.8@3179.92,3354.72 ; 3179.92,3398.07 J5.8@3179.92,3354.72 ; 3223.27,1554.72 J5.44@3179.92,1554.72 ; 3223.27,2154.72 J5.32@3179.92,2154.72 ; 3223.27,2754.72 J5.20@3179.92,2754.72 ; 3223.27,3354.72 J5.8@3179.92,3354.72
  BOTTOM w19.68: PP2.1@2362.2,157.48 2397.64,122.05 v1(2397.64,74.72)
5V: C2.1 C7.1 C8.1 C15.1 F1.2 J5.4 J5.56 J6.4 J6.56 PP3.1 R1.1 R2.1 R19.1 U1.1 U1.6 U1.7 U3.3 | length 1818.2
  TOP w7.87: v1(2275.59,231.22) U1.6@2275.59,250.98 ; v1(2448.03,408.94) 2448.03,382.09 R2.1@2448.23,381.89
  TOP w11.81: C15.1@456.69,2340.55 C15.1@456.69,2341.93 v1(456.69,2367.6) ; U1.1@2275.59,339.57 2275.59,381.89 C8.1@2287.4,393.7 ; C7.1@2397.64,196.85 2409.45,208.66 U1.7@2409.45,250.98
  TOP w15.75: v1(456.69,2367.6) 536.89,2367.6 U3.3@543.31,2374.02 ; v1(2713.5,456.69) F1.2@2795.28,456.69 v1(2795.28,412.32) ; v1(2933.07,395.59) C2.1@2933.07,433.07 v1(2983.35,433.07)
  TOP w19.68: v1(1653.54,64.88) R19.1@1653.54,100.39 ; v1(2248.03,401.58) 2255.91,393.7 C8.1@2287.4,393.7 ; C7.1@2397.64,196.85 2429.13,196.85 v1(2437.01,188.98)
  TOP w39.37: R1.1@1240.16,750 1240.16,703.74 1472.44,471.46 v1(1472.44,397.64)
  PWRT w8.46: 2636.58,954.72 J6.56@2679.92,954.72 ; 2636.58,3554.72 J6.4@2679.92,3554.72 ; 2679.92,911.38 J6.56@2679.92,954.72 ; 2679.92,998.07 J6.56@2679.92,954.72 ; 2679.92,3511.38 J6.4@2679.92,3554.72 ; 2679.92,3598.07 J6.4@2679.92,3554.72 ; 2723.27,954.72 J6.56@2679.92,954.72 ; 2723.27,3554.72 J6.4@2679.92,3554.72 ; 3136.58,954.72 J5.56@3179.92,954.72 ; 3136.58,3554.72 J5.4@3179.92,3554.72 ; 3179.92,911.38 J5.56@3179.92,954.72 ; 3179.92,998.07 J5.56@3179.92,954.72 ; 3179.92,3511.38 J5.4@3179.92,3554.72 ; 3179.92,3598.07 J5.4@3179.92,3554.72 ; 3223.27,954.72 J5.56@3179.92,954.72 ; 3223.27,3554.72 J5.4@3179.92,3554.72
  BOTTOM w19.68: v1(2795.28,412.32) PP3.1@2795.28,472.44
CAM0_CN: J1.144 J9.8 | length 2098.5
  TOP w4.57: v1(135.48,594.15) 151.92,594.15 162.5,604.73 192.51,604.73 J9.8@196.85,600.39 ; J1.144@1224.41,1718.5 1269.73,1718.5 1276.99,1725.77 1310.48,1725.77 v1(1321.46,1714.79)
  BOTTOM w4.57: v1(135.48,594.15) 151.92,594.15 162.5,604.73 346.86,604.73 370.12,627.99 370.12,1084.49 809.21,1523.58 925.35,1523.58 1127.14,1725.37 1294.45,1725.37 1305.02,1714.79 v1(1321.46,1714.79)
CAM0_CP: J1.142 J9.9 | length 2098.9
  TOP w4.57: v1(135.48,625.2) 151.91,625.2 162.5,614.61 191.39,614.61 J9.9@196.85,620.08 ; J1.142@1224.41,1742.13 1269.73,1742.13 1276.99,1734.86 1310.48,1734.86 v1(1321.46,1745.84)
  BOTTOM w4.57: v1(135.48,625.2) 151.91,625.2 162.5,614.61 342.76,614.61 360.24,632.09 360.24,1088.58 805.12,1533.47 921.26,1533.47 1123.05,1735.25 1294.45,1735.25 1305.03,1745.84 v1(1321.46,1745.84)
CAM0_DN0: J1.138 J9.2 | length 2106.8
  TOP w4.57: J9.2@196.85,482.28 223.39,482.28 228.29,487.18 250.97,487.18 287.05,523.27 287.05,673.78 297.63,684.35 v1(297.63,700.79) ; J1.138@1224.41,1789.37 1269.73,1789.37 1276.99,1796.63 1308.54,1796.63 v1(1321.26,1783.92)
  BOTTOM w4.57: v1(297.63,700.79) 297.63,717.22 287.04,727.8 287.04,1070.51 811.02,1594.49 911.42,1594.49 1111.43,1794.5 1294.25,1794.5 1304.83,1783.92 v1(1321.26,1783.92)
CAM0_DN1: J1.150 J9.5 | length 2099.5
  TOP w4.57: v1(135.48,535.1) 151.92,535.1 162.5,545.68 192.51,545.68 J9.5@196.85,541.34 ; J1.150@1224.41,1647.64 1269.73,1647.64 1276.99,1654.9 1310.48,1654.9 v1(1321.46,1643.93)
  BOTTOM w4.57: v1(135.48,535.1) 151.91,535.1 162.5,545.68 370.48,545.68 438.98,614.17 438.98,1080.71 811.02,1452.76 950.79,1452.76 1152.54,1654.51 1294.45,1654.51 1305.03,1643.93 v1(1321.46,1643.93)
CAM0_DP0: J1.136 J9.3 | length 2105.3
  TOP w4.57: J9.3@196.85,501.97 223.39,501.97 228.29,497.07 246.87,497.07 277.16,527.36 277.16,673.78 266.58,684.36 v1(266.58,700.79) ; J1.136@1224.41,1812.99 1269.73,1812.99 1276.99,1805.73 1312.03,1805.73 v1(1321.26,1814.96)
  BOTTOM w4.57: v1(266.58,700.79) 266.58,717.22 277.16,727.8 277.16,1074.6 806.93,1604.37 907.32,1604.37 1107.34,1804.38 1294.25,1804.38 1304.83,1814.96 v1(1321.26,1814.96)
CAM0_DP1: J1.148 J9.6 | length 2099.9
  TOP w4.57: v1(135.48,566.14) 151.91,566.14 162.5,555.56 191.39,555.56 J9.6@196.85,561.02 ; J1.148@1224.41,1671.26 1269.73,1671.26 1276.99,1664 1310.48,1664 v1(1321.46,1674.97)
  BOTTOM w4.57: v1(135.48,566.14) 151.92,566.14 162.5,555.56 366.39,555.56 429.09,618.27 429.09,1084.8 806.93,1462.64 946.69,1462.64 1148.45,1664.39 1294.45,1664.39 1305.02,1674.97 v1(1321.46,1674.97)
CAM0_IO0: J6.51 J9.17 | length 2979.9
  TOP w7.87: v1(145.67,755.9) 167.32,777.56 J9.17@196.85,777.56
  PWRB w7.87: v1(145.67,755.9) 188.98,755.9 212.6,732.28 346.46,732.28 665.35,1051.18 665.35,1165.35 937.01,1437.01 2297.64,1437.01 J6.51@2579.92,1154.72
CAM0_IO1: J6.49 J9.18 | length 2943.4
  TOP w7.87: v1(155.51,797.24) J9.18@196.85,797.24
  PWRB w7.87: v1(155.51,797.24) 356.3,797.24 643.7,1084.65 643.7,1289.37 812.09,1457.76 823.23,1457.76 2376.89,1457.76 J6.49@2579.92,1254.72
CAM1_CN: J1.149 J11.8 | length 855.6
  TOP w4.57: J11.8@196.85,1309.05 223.39,1309.05 228.29,1313.96 378.92,1313.96 731.28,1666.32 848.48,1666.32 855.35,1659.45 J1.149@901.58,1659.45
CAM1_CP: J1.147 J11.9 | length 855.6
  TOP w4.57: J11.9@196.85,1328.74 223.39,1328.74 228.29,1323.84 374.82,1323.84 727.18,1676.2 848.48,1676.2 855.35,1683.07 J1.147@901.58,1683.07
CAM1_DN0: J1.161 J11.2 | length 845.8
  TOP w4.57: J11.2@196.85,1190.95 223.39,1190.95 228.29,1195.85 448.01,1195.85 776.75,1524.59 848.48,1524.59 855.35,1517.72 J1.161@901.58,1517.72
CAM1_DN1: J1.155 J11.5 | length 850.7
  TOP w4.57: J11.5@196.85,1250 223.39,1250 228.29,1254.9 410.61,1254.9 751.16,1595.45 848.48,1595.45 855.35,1588.58 J1.155@901.58,1588.58
CAM1_DN2: J1.143 J11.11 | length 860.4
  TOP w4.57: J11.11@196.85,1368.11 223.39,1368.11 228.29,1373.01 345.65,1373.01 709.82,1737.18 848.48,1737.18 855.35,1730.32 J1.143@901.58,1730.32
CAM1_DN3: J1.137 J11.14 | length 865.3
  TOP w4.57: J11.14@196.85,1427.16 223.39,1427.16 228.29,1432.07 325.97,1432.07 701.95,1808.05 848.48,1808.05 855.35,1801.18 J1.137@901.58,1801.18
CAM1_DP0: J1.159 J11.3 | length 845.8
  TOP w4.57: J11.3@196.85,1210.63 223.39,1210.63 228.29,1205.73 443.92,1205.73 772.66,1534.47 848.48,1534.47 855.35,1541.34 J1.159@901.58,1541.34
CAM1_DP1: J1.153 J11.6 | length 850.7
  TOP w4.57: J11.6@196.85,1269.68 223.39,1269.68 228.29,1264.78 406.52,1264.78 747.07,1605.34 848.48,1605.34 855.35,1612.2 J1.153@901.58,1612.2
CAM1_DP2: J1.141 J11.12 | length 860.4
  TOP w4.57: J11.12@196.85,1387.8 223.39,1387.8 228.29,1382.89 341.56,1382.89 705.73,1747.07 848.48,1747.07 855.35,1753.94 J1.141@901.58,1753.94
CAM1_DP3: J1.135 J11.15 | length 865.3
  TOP w4.57: J11.15@196.85,1446.85 223.39,1446.85 228.29,1441.95 321.87,1441.95 697.85,1817.93 848.48,1817.93 855.35,1824.8 J1.135@901.58,1824.8
CAM1_IO0: J6.43 J11.17 | length 2439.5
  TOP w7.87: J11.17@196.85,1486.22 v1(261.81,1486.22)
  PWRB w7.87: v1(261.81,1486.22) 561.02,1486.22 663.39,1588.58 2546.06,1588.58 J6.43@2579.92,1554.72
CAM1_IO1: J6.41 J11.18 | length 2521.1
  TOP w7.87: v1(159.45,1505.91) J11.18@196.85,1505.91
  PWRB w7.87: v1(159.45,1505.91) 545.28,1505.91 645.67,1606.3 1268.5,1606.3 1270.47,1604.33 1286.78,1604.33 1288.75,1606.3 2531.5,1606.3 J6.41@2579.92,1654.72
CD0_SCL: J6.47 J9.20 J10.20 R13.2 | length 5473.2
  TOP w7.87: v1(94.49,2903.54) 114.17,2923.23 J10.20@196.85,2923.23 286.22,2923.23 314.96,2951.97 R13.2@314.96,2973.03 ; v1(110.24,818.9) 127.95,836.61 J9.20@196.85,836.61
  PWRT w7.87: v1(94.49,2903.54) 208.66,2789.37 208.66,960.63 110.24,862.21 v1(110.24,818.9)
  PWRB w7.87: v1(110.24,818.9) 173.23,818.9 192.91,838.58 338.58,838.58 620.08,1120.08 620.08,1324.8 811.02,1515.75 2418.9,1515.75 J6.47@2579.92,1354.72
CD0_SDA: J6.45 J9.21 J10.21 R14.2 | length 5435.2
  TOP w7.87: v1(76.77,2942.91) J10.21@196.85,2942.91 245.47,2942.91 R14.2@275.59,2973.03 ; v1(78.74,856.3) J9.21@196.85,856.3
  PWRT w7.87: v1(76.77,2942.91) 63.49,2929.63 63.49,2901.08 188.98,2775.59 188.98,966.54 v1(78.74,856.3)
  PWRB w7.87: v1(78.74,856.3) 281.5,856.3 596.46,1171.26 596.46,1336.61 799.21,1539.37 2495.28,1539.37 J6.45@2579.92,1454.72
CD1_SCL: J6.39 J11.20 J12.20 R16.2 | length 4965.5
  TOP w5.91: J12.20@196.85,3631.89 225.39,3631.89 267.72,3674.21 R16.2@267.72,3709.25
  TOP w7.87: v1(162.32,3631.89) J12.20@196.85,3631.89 ; v1(163.39,1545.28) J11.20@196.85,1545.28
  PWRB w7.87: v1(162.32,3631.89) 208.66,3585.55 208.66,2492.13 224.41,2476.38 224.41,1712.6 v1(259.84,1677.16) ; v1(163.39,1545.28) 541.34,1545.28 814.96,1818.9 874.02,1818.9 921.26,1866.14 2468.5,1866.14 J6.39@2579.92,1754.72
  BOTTOM w7.87: v1(163.39,1545.28) 163.39,1600.39 240.16,1677.16 v1(259.84,1677.16)
CD1_SDA: J6.37 J11.21 J12.21 R17.2 | length 4947.3
  TOP w5.91: J12.21@196.85,3651.58 225.39,3651.58 234.47,3660.65 234.47,3679.11 224.41,3689.17 R17.2@224.41,3709.25
  TOP w7.87: v1(133.86,1564.96) J11.21@196.85,1564.96 ; v1(139.76,3651.58) J12.21@196.85,3651.58
  PWRB w7.87: v1(139.76,3651.58) 139.76,3612.21 188.98,3562.99 188.98,2484.26 202.76,2470.47 202.76,1679.14 133.86,1610.24 v1(133.86,1564.96) 501.97,1564.96 822.84,1885.83 2548.82,1885.83 J6.37@2579.92,1854.72
CEC: J13.13 Q3.3 U4.A2 | length 271.8
  TOP w7.87: v1(317.44,2125.98) J13.13@383.47,2125.98 463.27,2125.98 492.13,2154.84 ; U4.A2@492.13,2169.29 492.13,2154.84 ; Q3.3@559.06,2145.67 501.3,2145.67 492.13,2154.84
CM_1V8: C10.1 J1.183 J1.184 J1.185 J1.186 R5.2 | length 481.2
  TOP w11.81: J1.185@901.58,1234.25 v1(847.36,1234.25) 812.99,1234.25 C10.1@787.4,1259.84 821.85,1259.84 823.82,1257.87 J1.183@901.58,1257.87 v1(955.79,1257.87) ; v1(1170.2,1246.06) J1.184@1224.41,1246.06 ; J1.186@1224.41,1222.44 v1(1278.62,1222.44)
  TOP w19.68: v1(1492.13,824.8) R5.2@1535.43,824.8 v1(1535.43,860.32)
CM_3V3: C3.1 J1.191 J1.192 J1.193 J1.194 R4.2 | length 445.1
  TOP w11.81: J1.193@901.58,1139.76 v1(847.36,1139.76) 825.71,1161.42 821.85,1161.42 823.82,1163.39 J1.191@901.58,1163.39 v1(955.79,1163.39) ; v1(1170.2,1151.58) J1.192@1224.41,1151.58 ; J1.194@1224.41,1127.95 v1(1278.62,1127.95)
  TOP w19.68: C3.1@787.4,1161.42 821.85,1161.42 ; v1(1338.58,860.32) R4.2@1338.58,824.8 v1(1381.89,824.8)
CM_VBAT: C1.1 J1.197 J1.198 J1.199 J1.200 R1.2 | length 470.7
  TOP w11.81: C1.1@787.4,1062.99 C1.1@801.18,1062.99 ; J1.197@901.58,1092.52 v1(847.36,1092.52) 830.71,1092.52 C1.1@801.18,1062.99 ; v1(955.79,1068.9) J1.199@901.58,1068.9 842.6,1068.9 836.69,1062.99 C1.1@801.18,1062.99 ; v1(1170.2,1057.09) J1.200@1224.41,1057.09 ; J1.198@1224.41,1080.71 v1(1278.62,1080.71)
  TOP w19.68: v1(1196.85,824.8) R1.2@1240.16,824.8 v1(1240.16,860.32)
CM_VDAC: J1.189 J1.190 R6.2 | length 992.2
  TOP w11.81: v1(847.36,1187.01) J1.189@901.58,1187.01 ; J1.190@1224.41,1175.2 v1(1278.62,1175.2)
  TOP w19.68: R6.2@1437.01,824.8 v1(1437.01,860.32)
  PWRB w11.81: v1(847.36,1187.01) 978.35,1187.01 990.16,1175.2 v1(1278.62,1175.2)
  PWRB w19.68: v1(1278.62,1175.2) 1332.68,1175.2 1437.01,1070.87 v1(1437.01,860.32)
DAC_2V5: C5.1 PP4.1 R6.1 U2.5 | length 498.2
  TOP w11.81: U2.5@1657.48,537.4 1657.48,578.74 C5.1@1645.67,590.55 v1(1679.21,590.55)
  TOP w19.68: R6.1@1437.01,750 1437.01,700.79 1484.25,653.54 1617.2,653.54 1645.67,625.08 C5.1@1645.67,590.55
  BOTTOM w19.68: v1(1679.21,590.55) 1700.79,590.55 PP4.1@1744.09,547.24
DSI0_CN: J1.105 J10.8 | length 1270.6
  TOP w4.57: v1(120.35,2680.29) 131.97,2691.91 149.76,2691.91 165.41,2691.91 170.31,2687.01 J10.8@196.85,2687.01 ; v1(714.9,2381.55) 698.47,2381.55 681.14,2364.22 681.14,2204.68 713.56,2172.26 753.94,2172.26 758.84,2177.16 772.66,2177.16 777.56,2172.26 785.43,2172.26 793.31,2180.14 801.18,2180.14 809.06,2172.26 816.93,2172.26 824.8,2180.14 832.68,2180.14 840.55,2172.26 848.48,2172.26 855.35,2179.13 J1.105@901.58,2179.13
  BOTTOM w4.57: v1(120.35,2680.29) 131.97,2691.91 353.17,2691.91 669.66,2375.42 692.35,2375.42 698.48,2381.55 v1(714.9,2381.55)
DSI0_CP: J1.107 J10.9 | length 1269.9
  TOP w4.57: v1(120.35,2713.41) 131.97,2701.79 145.66,2701.79 165.41,2701.79 170.31,2706.69 J10.9@196.85,2706.69 ; v1(691.49,2404.97) 691.49,2388.54 671.26,2368.32 671.26,2200.59 709.47,2162.38 848.48,2162.38 855.35,2155.51 J1.107@901.58,2155.51
  BOTTOM w4.57: v1(120.35,2713.41) 131.97,2701.79 357.27,2701.79 673.75,2385.3 688.26,2385.3 691.49,2388.53 v1(691.49,2404.97)
DSI0_DN0: J1.99 J10.2 | length 1273.3
  TOP w4.57: v1(132.16,2562.18) 143.78,2573.8 165.41,2573.8 170.31,2568.9 J10.2@196.85,2568.9 ; v1(740.16,2254.75) 751.78,2243.13 770.39,2243.13 774.96,2247.7 774.96,2251.34 779.52,2255.91 788.66,2255.91 793.22,2251.34 793.22,2247.7 797.79,2243.13 806.92,2243.13 811.49,2247.7 811.49,2253.31 816.06,2257.87 825.19,2257.87 829.76,2253.31 829.76,2247.7 834.33,2243.13 848.48,2243.13 855.35,2250 J1.99@901.58,2250
  BOTTOM w4.57: v1(132.16,2562.18) 120.55,2573.8 97.62,2573.8 78.78,2554.96 78.78,2502.13 134.02,2446.89 148.24,2446.89 158.59,2436.53 158.59,2416.02 163.16,2411.46 172.3,2411.46 176.86,2416.02 176.86,2436.53 187.22,2446.89 204.54,2446.89 214.89,2436.53 214.89,2416.02 219.46,2411.46 228.59,2411.46 233.16,2416.02 233.16,2436.53 243.52,2446.89 439.13,2446.89 642.89,2243.13 728.54,2243.13 v1(740.16,2254.75)
DSI0_DN1: J1.93 J10.5 | length 1259
  TOP w4.57: J10.5@196.85,2627.95 223.39,2627.95 228.29,2632.85 266.75,2632.85 318.9,2580.71 318.9,2561.02 280.85,2522.98 v1(264.42,2522.98) ; v1(740.16,2325.61) 751.78,2314 785.49,2314 793.36,2321.87 801.24,2321.87 809.11,2314 816.98,2314 824.86,2321.87 832.73,2321.87 840.61,2314 848.48,2314 855.35,2320.87 J1.93@901.58,2320.87
  BOTTOM w4.57: v1(264.42,2522.98) 280.85,2522.98 334.68,2576.81 374.17,2576.81 398.69,2552.3 405.15,2552.3 421.07,2568.22 435.72,2568.22 447.97,2555.97 447.97,2541.32 432.05,2525.39 432.05,2518.94 438.51,2512.48 444.97,2512.48 460.89,2528.4 475.54,2528.4 487.79,2516.15 487.79,2501.5 471.87,2485.58 471.87,2479.12 478.33,2472.66 484.78,2472.66 500.71,2488.58 515.35,2488.58 527.61,2476.33 527.61,2461.68 511.68,2445.76 511.68,2439.3 518.15,2432.84 524.6,2432.84 540.53,2448.76 555.17,2448.76 567.43,2436.51 567.43,2421.86 551.5,2405.94 551.5,2399.48 636.98,2314 728.54,2314 v1(740.16,2325.61)
DSI0_DP0: J1.101 J10.3 | length 1272.4
  TOP w4.57: v1(132.16,2595.3) 143.78,2583.68 165.41,2583.68 170.31,2588.58 J10.3@196.85,2588.58 ; v1(740.16,2221.63) 751.77,2233.25 848.48,2233.25 855.35,2226.38 J1.101@901.58,2226.38
  BOTTOM w4.57: v1(132.16,2595.3) 120.54,2583.68 93.52,2583.68 68.9,2559.05 68.9,2498.03 129.92,2437.01 144.15,2437.01 148.71,2432.44 148.71,2411.93 159.07,2401.58 176.39,2401.58 186.74,2411.93 186.74,2432.44 191.31,2437.01 200.44,2437.01 205.01,2432.44 205.01,2411.93 215.37,2401.58 232.69,2401.58 243.04,2411.93 243.04,2432.44 247.61,2437.01 435.04,2437.01 638.8,2233.25 728.54,2233.25 v1(740.16,2221.63)
DSI0_DP1: J1.95 J10.6 | length 1262.4
  TOP w4.57: J10.6@196.85,2647.64 223.39,2647.64 228.29,2642.74 270.85,2642.74 328.78,2584.8 328.78,2556.93 287.84,2515.99 v1(287.84,2499.56) ; v1(740.16,2292.5) 751.77,2304.11 848.48,2304.11 855.35,2297.24 J1.95@901.58,2297.24
  BOTTOM w4.57: v1(287.84,2499.56) 287.84,2516 338.77,2566.93 370.08,2566.93 394.59,2542.41 409.24,2542.41 425.16,2558.34 431.62,2558.34 438.09,2551.87 438.09,2545.41 422.16,2529.49 422.16,2514.84 434.41,2502.6 449.06,2502.6 464.98,2518.52 471.44,2518.52 477.91,2512.05 477.91,2505.6 461.98,2489.67 461.98,2475.02 474.23,2462.78 488.88,2462.78 504.8,2478.7 511.26,2478.7 517.73,2472.23 517.73,2465.78 501.8,2449.85 501.8,2435.2 514.05,2422.96 528.7,2422.96 544.62,2438.88 551.08,2438.88 557.55,2432.41 557.55,2425.96 541.62,2410.03 541.62,2395.39 632.89,2304.12 728.54,2304.12 v1(740.16,2292.5)
DSI1_CN: J1.102 J12.8 | length 2169.2
  TOP w4.53: J1.102@1224.41,2214.57 1269.72,2214.57 1277,2221.85 1310.14,2221.85 v1(1321.26,2210.73)
  TOP w4.57: J12.8@196.85,3395.67 223.39,3395.67 228.29,3400.57 494.29,3400.57 v1(505.91,3388.95)
  BOTTOM w4.57: v1(505.91,3388.95) 517.52,3400.57 530.53,3400.57 547.24,3383.86 547.24,3338.83 542.68,3334.26 526.1,3334.26 515.75,3323.91 515.75,3306.58 526.1,3296.23 542.68,3296.23 547.24,3291.66 547.24,3282.53 542.68,3277.96 526.1,3277.96 515.75,3267.61 515.75,3250.28 526.1,3239.93 542.68,3239.93 547.24,3235.36 547.24,2795.28 824.8,2517.72 864.17,2517.72 1160.6,2221.29 1294.27,2221.29 1304.83,2210.73 v1(1321.26,2210.73)
DSI1_CP: J1.100 J12.9 | length 2169.1
  TOP w4.53: J1.100@1224.41,2238.19 1269.72,2238.19 1277,2230.91 1310.43,2230.91 v1(1321.26,2241.73)
  TOP w4.57: J12.9@196.85,3415.35 223.39,3415.35 228.29,3410.45 494.29,3410.45 v1(505.91,3422.07)
  BOTTOM w4.57: v1(505.91,3422.07) 517.52,3410.45 534.63,3410.45 557.13,3387.95 557.13,3334.73 546.77,3324.38 530.2,3324.38 525.63,3319.81 525.63,3310.68 530.2,3306.11 546.77,3306.11 557.13,3295.76 557.13,3278.43 546.77,3268.08 530.2,3268.08 525.63,3263.51 525.63,3254.38 530.2,3249.81 546.77,3249.81 557.13,3239.46 557.13,2799.37 828.9,2527.6 868.27,2527.6 1164.69,2231.17 1294.27,2231.17 1304.83,2241.73 v1(1321.26,2241.73)
DSI1_DN0: J1.96 J12.2 | length 2162.4
  TOP w4.53: J1.96@1224.41,2285.43 1269.72,2285.43 1277,2292.72 1310.25,2292.72 v1(1321.22,2281.74)
  TOP w4.57: J12.2@196.85,3277.56 223.39,3277.56 228.29,3282.46 586.81,3282.46 v1(598.42,3270.85)
  BOTTOM w4.57: v1(598.42,3270.85) 610.04,3282.46 626.98,3282.46 659.45,3250 659.45,3191.41 654.88,3186.84 624.53,3186.84 614.17,3176.49 614.17,3159.17 624.53,3148.81 654.88,3148.81 659.45,3144.24 659.45,3135.11 654.88,3130.54 624.53,3130.54 614.17,3120.19 614.17,3102.87 624.53,3092.51 654.88,3092.51 659.45,3087.95 659.45,3078.81 654.88,3074.24 624.53,3074.24 614.17,3063.89 614.17,3046.57 624.53,3036.21 654.88,3036.21 659.45,3031.65 659.45,2757.87 826.77,2590.55 864.17,2590.55 1162.42,2292.3 1294.23,2292.3 1304.79,2281.74 v1(1321.22,2281.74)
DSI1_DN1: J1.120 J12.5 | length 2171.9
  TOP w4.53: J1.120@1224.41,2001.97 1269.72,2001.97 1277,2009.25 1310.25,2009.25 v1(1321.22,1998.28)
  TOP w4.57: J12.5@196.85,3336.61 223.39,3336.61 228.29,3341.52 244.91,3341.52 262.71,3341.51 v1(274.32,3329.9)
  BOTTOM w4.57: v1(274.32,3329.9) 285.93,3341.51 323.65,3341.51 364.13,3301.02 364.13,3256.05 359.57,3251.48 348.94,3251.48 338.58,3241.13 338.58,3223.8 348.94,3213.45 359.57,3213.45 364.13,3208.88 364.13,3199.75 359.57,3195.18 348.94,3195.18 338.58,3184.83 338.58,3167.5 348.94,3157.15 359.57,3157.15 364.13,3152.58 364.13,2775.43 832.52,2307.05 864.02,2307.05 1162.22,2008.84 1294.23,2008.84 1304.79,1998.28 v1(1321.22,1998.28)
DSI1_DN2: J1.114 J12.11 | length 2166
  TOP w4.53: J1.114@1224.41,2072.84 1269.72,2072.84 1277,2080.12 1310.14,2080.12 v1(1321.26,2069)
  TOP w4.57: J12.11@196.85,3454.72 223.39,3454.72 228.29,3459.63 262.71,3459.63 v1(274.32,3448.01)
  BOTTOM w4.57: v1(274.32,3448.01) 285.94,3459.63 343.52,3459.63 411.42,3391.73 411.42,2795.28 830.71,2375.98 870.08,2375.98 1166.5,2079.56 1294.27,2079.56 1304.83,2069 v1(1321.26,2069)
DSI1_DN3: J1.108 J12.14 | length 2164
  TOP w4.53: J1.108@1224.41,2143.7 1269.72,2143.7 1277,2150.98 1310.25,2150.98 v1(1321.22,2140.01)
  TOP w4.57: J12.14@196.85,3513.78 223.39,3513.78 228.29,3518.68 250.49,3518.68 v1(260.38,3508.79)
  BOTTOM w4.57: v1(260.38,3508.79) 270.27,3518.68 349.23,3518.68 458.66,3409.25 458.66,2804.92 812.84,2450.75 864.02,2450.75 1164.19,2150.57 1294.23,2150.57 1304.79,2140.01 v1(1321.22,2140.01)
